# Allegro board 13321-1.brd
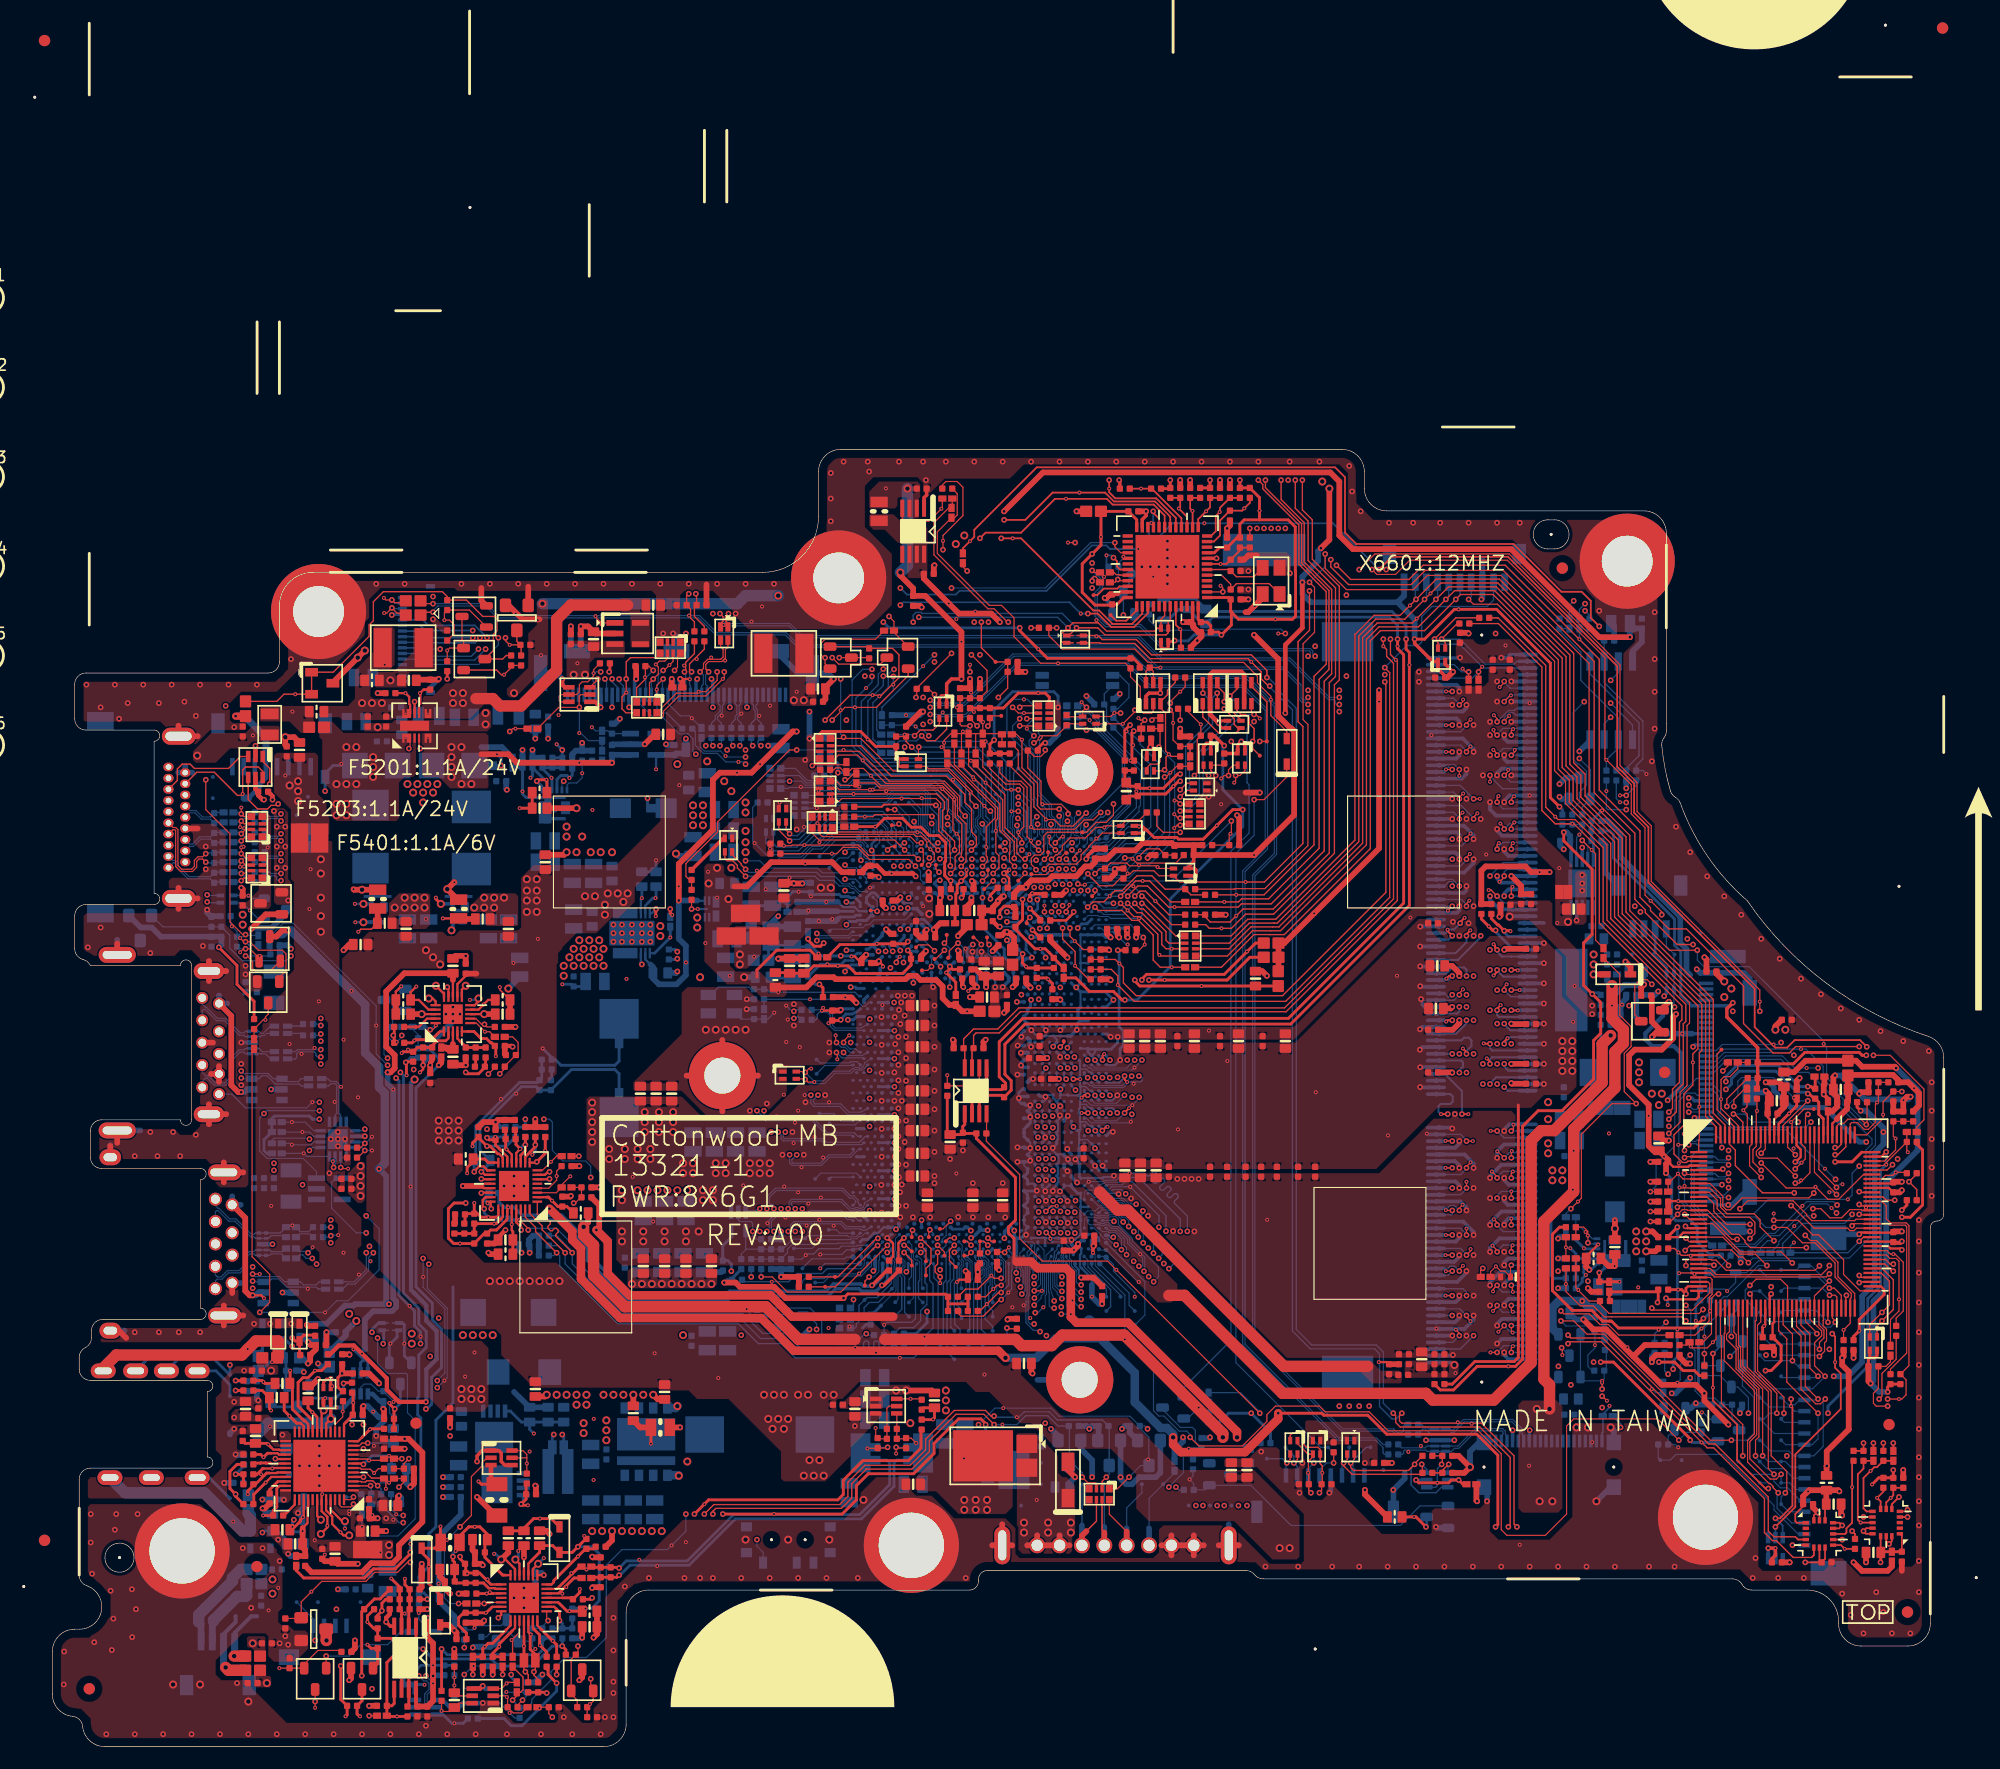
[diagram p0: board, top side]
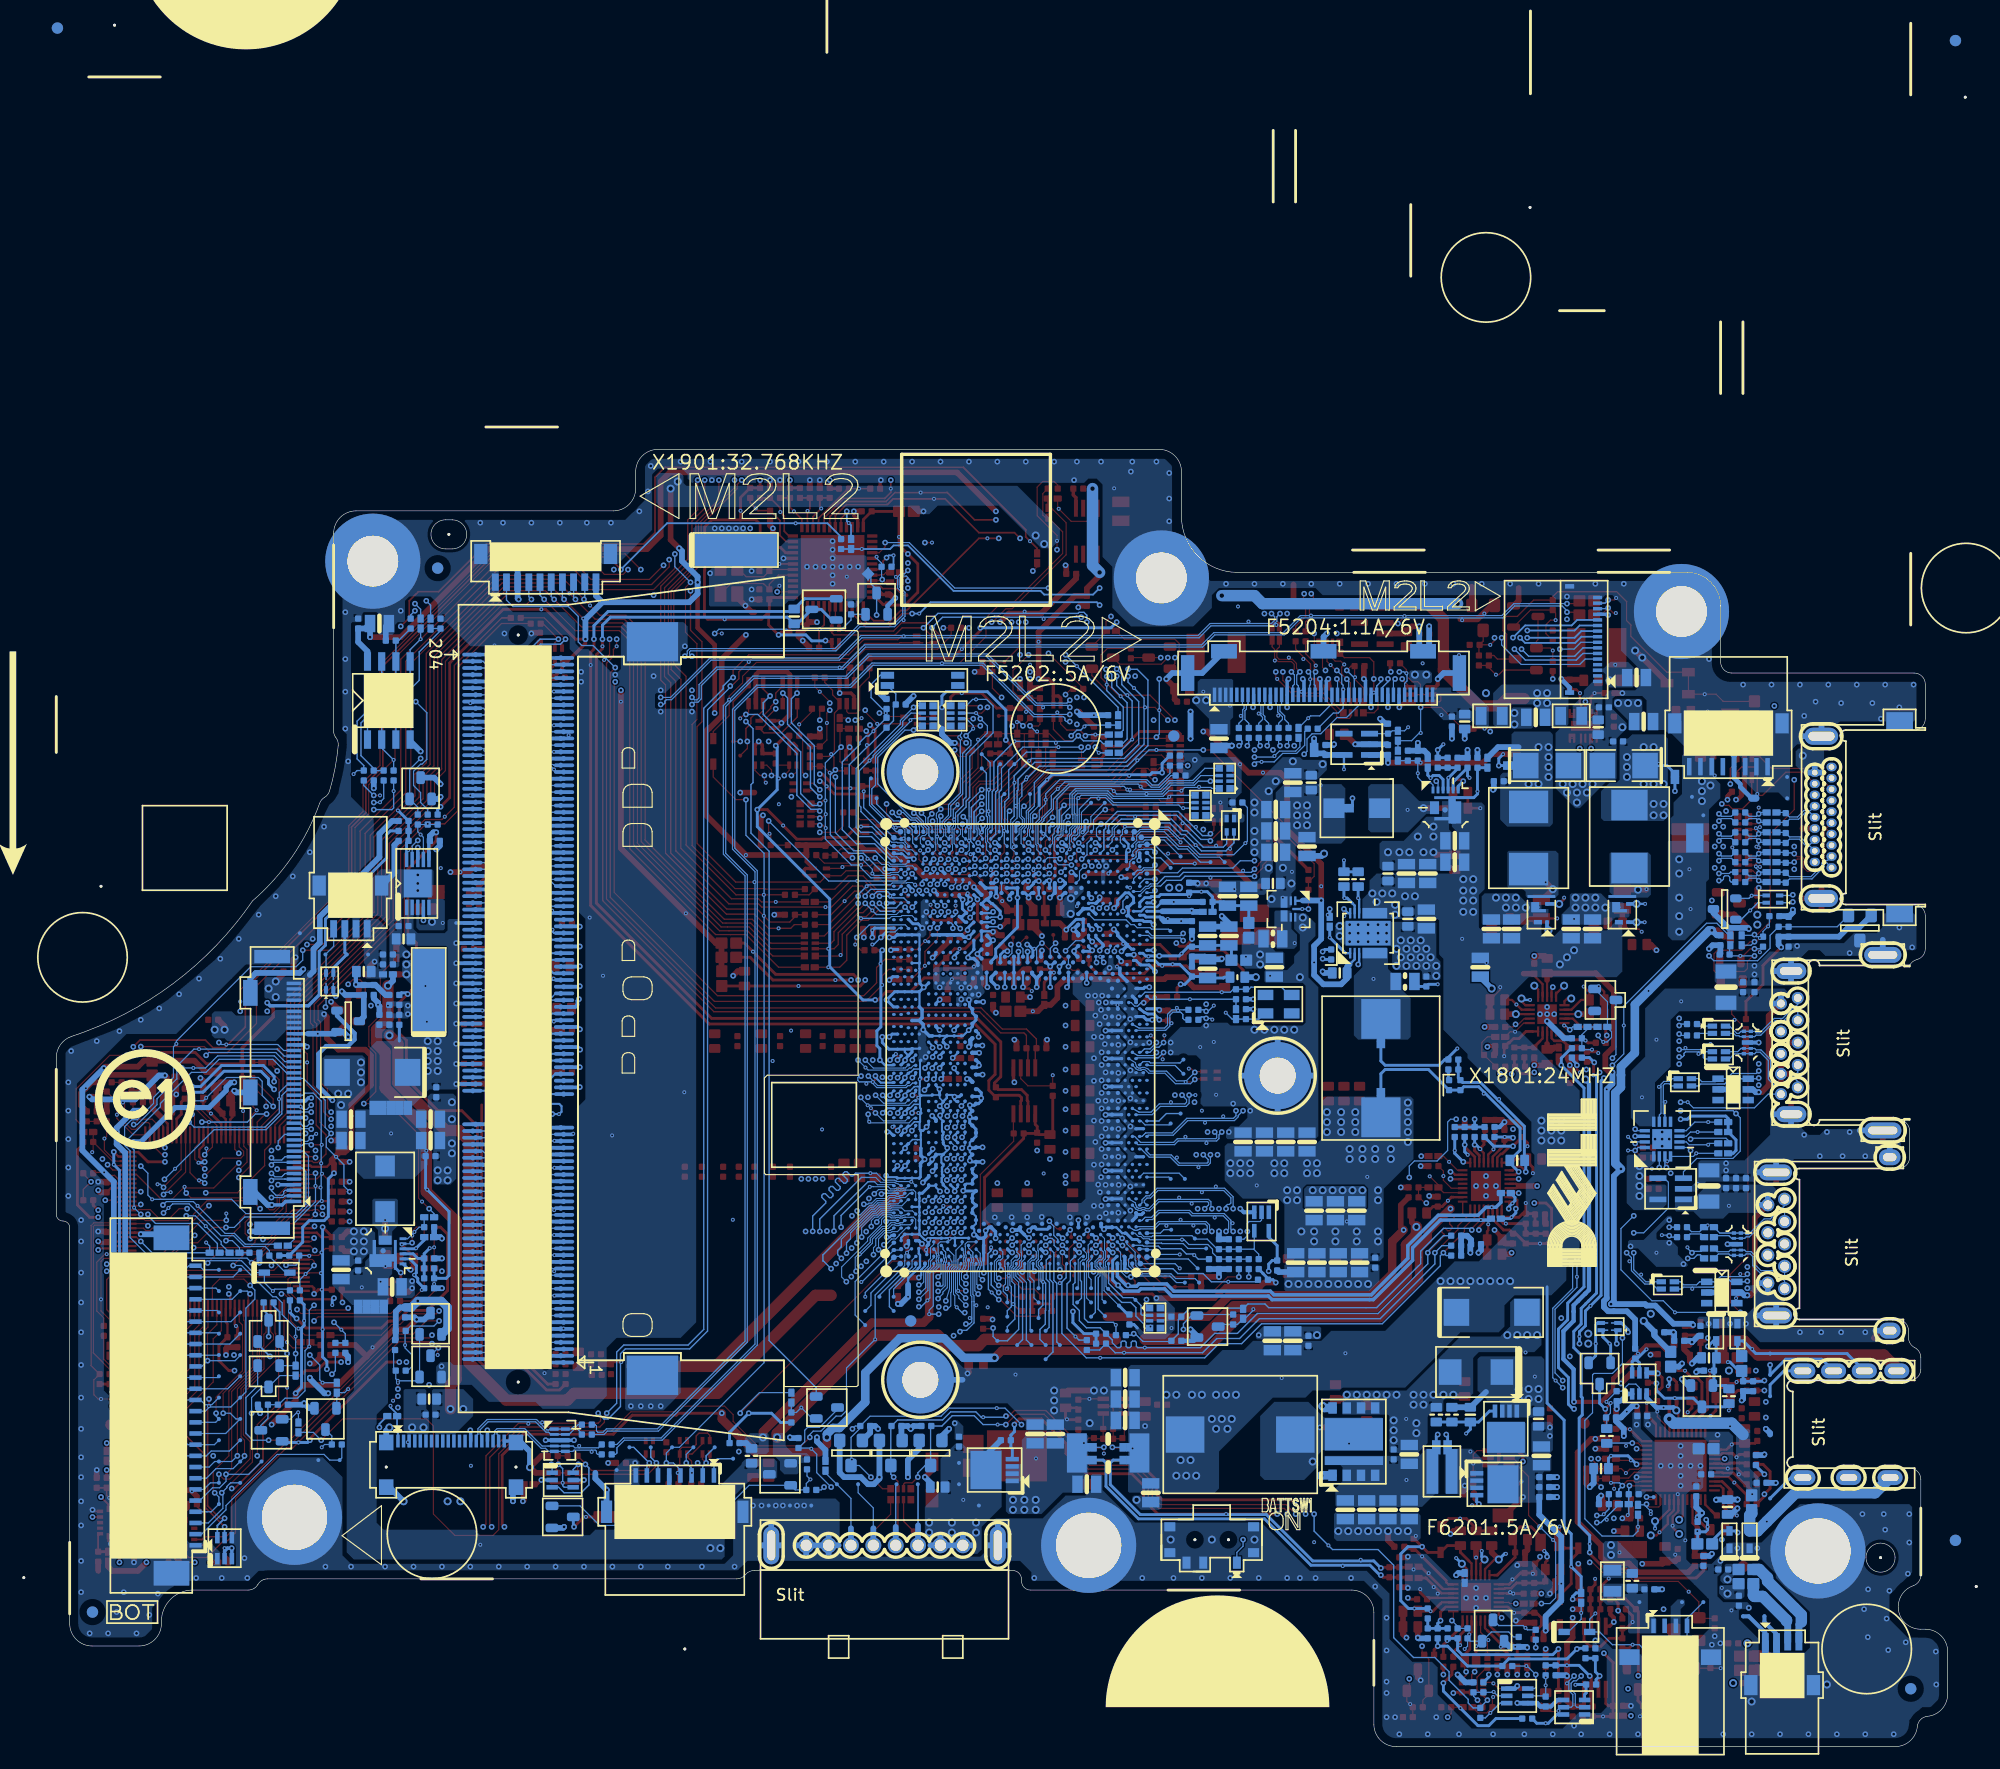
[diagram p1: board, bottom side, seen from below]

Outline 169.1 x 116 mm; copper layers: TOP, L2VCC, L3, L4, L5GND, BOTTOM. Coordinates in mm from the lower left corner of the outline.
Outline path: 0,8.5 0,4.7 arc(0.52,3.35) 1.81,2.71 arc(2.42,2.42) 2.71,1.81 arc(3.35,0.52) 4.7,0 49.3,0 arc(50.71,0.59) 51.3,2 51.3,12 arc(51.89,13.41) 53.3,14 82,14 arc(82.57,14.23) 82.8,14.8 82.8,14.95 arc(83.03,15.52) 83.6,15.75 106.71,15.75 arc(107.14,15.65) 107.49,15.37 arc(107.84,15.1) 108.27,15 150.21,15 arc(150.71,14.87) 151.07,14.5 arc(151.44,14.13) 151.94,14 156.9,14 arc(158.88,13.18) 159.7,11.2 159.7,11 arc(160.29,9.59) 161.7,9 165.9,9 arc(167.31,9.59) 167.9,11 167.9,46.4 arc(168.08,46.82) 168.5,47 arc(168.92,47.18) 169.1,47.6 169.1,61.61 arc(168.72,62.78) 167.72,63.51 arc(158.64,68.24) 151.55,75.63 arc(147.99,79.61) 145.55,84.36 arc(145.38,84.66) 145.12,84.88 arc(144.84,85.13) 144.67,85.46 arc(144.18,87.47) 143.89,89.52 arc(143.93,89.89) 144.1,90.23 arc(144.26,90.53) 144.31,90.87 arc(144.3,91.18) 144.3,91.5 144.3,108.5 arc(143.71,109.91) 142.3,110.5 119.3,110.5 arc(117.89,111.09) 117.3,112.5 117.3,114 arc(116.71,115.41) 115.3,116 70.5,116 arc(69.09,115.41) 68.5,114 68.5,110 arc(67.04,106.46) 63.5,105 23.3,105 arc(21.18,104.12) 20.3,102 20.3,97 arc(20.01,96.29) 19.3,96 3,96 arc(2.29,95.71) 2,95 2,91.9 arc(2.29,91.19) 3,90.9 9.1,90.9 arc(9.6,90.4) 9.1,89.9 9.1,76.3 arc(9.6,75.8) 9.1,75.3 3,75.3 arc(2.29,75.01) 2,74.3 2,71.35 arc(2.21,70.74) 2.75,70.38 arc(3.13,70.19) 3.4,69.85 11.45,69.85 arc(11.95,70.35) 12.45,69.85 12.45,56.05 arc(11.95,55.55) 11.45,56.05 4.4,56.05 arc(3.69,55.76) 3.4,55.05 3.4,52.7 arc(3.69,51.99) 4.4,51.7 13.25,51.7 arc(13.75,51.2) 13.25,50.7 13.25,39.2 arc(13.75,38.7) 13.25,38.2 4.5,38.2 arc(3.79,37.91) 3.5,37.2 3.5,36.58 arc(3.35,36.05) 2.95,35.68 arc(2.55,35.31) 2.4,34.79 2.4,33.75 arc(2.69,33.04) 3.4,32.75 13.85,32.75 arc(14.35,32.25) 13.85,31.75 13.85,25.9 arc(14.35,25.4) 13.85,24.9 3.4,24.9 arc(2.69,24.61) 2.4,23.9 2.4,15.34 arc(2.59,14.76) 3.07,14.39 arc(4.39,12.17) 2.42,10.5 2,10.5 arc(0.59,9.91) 0,8.5 ; 4.7,16.9 arc(6,18.2) 7.3,16.9 arc(6,15.6) 4.7,16.9 ; 8.7,17.5 arc(11.6,20.4) 14.5,17.5 arc(11.6,14.6) 8.7,17.5 ; 21.55,101.5 arc(23.8,103.75) 26.05,101.5 arc(23.8,99.25) 21.55,101.5 ; 58.3,60 arc(59.9,61.6) 61.5,60 arc(59.9,58.4) 58.3,60 ; 68.05,104.5 arc(70.3,106.75) 72.55,104.5 arc(70.3,102.25) 68.05,104.5 ; 73.9,18 arc(76.8,20.9) 79.7,18 arc(76.8,15.1) 73.9,18 ; 90.25,87.15 arc(91.85,88.75) 93.45,87.15 arc(91.85,85.55) 90.25,87.15 ; 90.25,32.8 arc(91.85,34.4) 93.45,32.8 arc(91.85,31.2) 90.25,32.8 ; 133.7,109.7 134.3,109.7 arc(135.6,108.4) 134.3,107.1 133.7,107.1 arc(132.4,108.4) 133.7,109.7 ; 138.55,106 arc(140.8,108.25) 143.05,106 arc(140.8,103.75) 138.55,106 ; 144.9,20.5 arc(147.8,23.4) 150.7,20.5 arc(147.8,17.6) 144.9,20.5

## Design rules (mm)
constraint set DEFAULT: min track width 0.127, pair gap 0.102
net group 85_USB6-DIFF165: nets USB_PN6 USB_PP6
net group AUDIO_SLEEVE-MWS: nets RING2_R SLEEVE_R
net group CLK_PCI_KBC: nets CLK_PCI_KBC CLK_PCI_KBC_R
net group CLK_PCI_LPC: nets CLK_PCI_LPC CLK_PCI_LPC_R
net group EDP_AUX: nets EDP_AUX EDP_AUX_DP
net group EDP_AUX#: nets EDP_AUX# EDP_AUX_DN
net group EDP_TX0: nets EDP_TX0 EDP_TX0_DP
net group EDP_TX0#: nets EDP_TX0# EDP_TX0_DN
net group EDP_TX1: nets EDP_TX1 EDP_TX1_DP
net group EDP_TX1#: nets EDP_TX1# EDP_TX1_DN
net group GND-MW: nets EC_AGND MIC_GND
net group HDA_CODEC_RST#: nets HDA_CODEC_RST# HDA_RST#
net group HDA_CODEC_SDIN0: nets HDA_CODEC_SDIN0 HDA_SDIN0
net group HDA_CODEC_SYNC: nets HDA_CODEC_SYNC HDA_SYNC
net group LPC_AD0: nets LPC_AD0 LPC_LAD0_PCH
net group LPC_AD1: nets LPC_AD1 LPC_LAD1_PCH
net group LPC_AD2: nets LPC_AD2 LPC_LAD2_PCH
net group LPC_AD3: nets LPC_AD3 LPC_LAD3_PCH
net group LPC_FRAME#: nets LPC_FRAME# LPC_LFRAME#_PCH
net group P26_FAN-MWS: nets FAN_PWM1 FAN_PWM1_C
net group PCH_SPI_DQ2: nets PCH_SPI_DQ2 SPI_WP#
net group PCH_SPI_DQ3: nets PCH_SPI_DQ3 SPI_HOLD#
net group PCIE_PTX_WLANRX_N3: nets PCIE_PTX_WLANRX_N3 PCIE_PTX_WLANRX_N3_C
net group PCIE_PTX_WLANRX_P3: nets PCIE_PTX_WLANRX_P3 PCIE_PTX_WLANRX_P3_C
net group PWR_VCC_GFB: nets PWR_VCC_GFB VSS_SENSE
net group PWR_VCC_VFB: nets PWR_VCC_VFB VCC_SENSE
net group T10_DDR3_A_ODT-MWS: nets M_A_DIMA_ODT0 M_A_DIMA_ODT1
net group USB30_RXDN1_C: nets USB3_PRX_CTX_N1 USB30_RXDN1_C
net group USB30_RXDP1_C: nets USB3_PRX_CTX_P1 USB30_RXDP1_C
net group USB30_TXDN0_R: nets USB3_PTX_CRX_N0 USB30_TXDN0_R
net group USB30_TXDP0_R: nets USB3_PTX_CRX_P0 USB30_TXDP0_R
net group USB_3+: nets USB_3+ USB_PP3
net group USB_3-: nets USB_3- USB_PN3
net group USB_PN1: nets USB_PN1 USB_PN1_R
net group USB_PP1: nets USB_PP1 USB_PP1_R
net group 50_CFG-MWS: nets CFG0 CFG1 CFG2 CFG3 CFG4 CFG5 CFG6 CFG7 CFG8 CFG9 CFG10 CFG11 CFG12 CFG13 CFG14 CFG15 CFG16 CFG17 CFG18 CFG19
net group 50_CLK-MWS: nets SUS_CLK SUS_CLK_PCH SUSCLK_KBC TP_CL_RST#
net group 50_INTEL_SIDEBAND-MWS: nets H_CATERR# H_CPUPWRGD H_PECI H_PROCHOT# H_PROCHOT#_EC H_PROCHOT#_R H_RCIN# PCH_PWROK PCH_THERMTRIP PECI PM_RSMRST# PQ4405_3 PQ4406_D PQ4413_3 PROCHOT#_BQ24770 PROCHOT_EC RTC_RST# SYS_PWROK
net group 50_JTAG-MWS: nets PCH_JTAG_TCK PCH_JTAG_TDI PCH_JTAG_TDO PCH_JTAG_TMS PCH_JTAG_TRST#
net group 50_LCD_BKLT-MWS: nets BKLT_CTRL EDP_BRIGHTNESS L_BKLT_CTRL LCD_BRIGHTNESS
net group 50_LPC-MWS: nets INT_SERIRQ
net group 50_SVID-MWS: nets H_CPU_SVIDALRT# H_CPU_SVIDCLK H_CPU_SVIDDAT VR_SVID_ALERT#
net group 50_XDP-MWS: nets XDP_DBRESET# XDP_PRDY# XDP_PREQ# XDP_TCK_JTAGX XDP_TCLK XDP_TDI XDP_TDO XDP_TMS XDP_TRST#
net group 50_XDP_BPM-MWS: nets XDP_BPM0 XDP_BPM1 XDP_BPM2 XDP_BPM3 XDP_BPM4 XDP_BPM5 XDP_BPM6 XDP_BPM7
net group 50_XTAL-MWS: nets MCU_OSCI MCU_OSCO RTC_X1 RTC_X2 XTAL24_IN XTAL24_IN_R XTAL24_OUT
net group AUDIO_OTHER-MWS: nets AMP_MUTE# COMBO-GPI EAPD# JDREF MUTE_CTRL
net group AUDIO_POWER_20-MW: nets +3V_1D5V_AVDD
net group AUDIO_T10_BEEP-MWS: nets AUD_HP1_JACK_L AUD_HP1_JACK_L1 AUD_HP1_JACK_R AUD_HP1_JACK_R1 AUD_PC_BEEP AUD_PC_BEEP_C AUD_PORTA_L_R_B AUD_PORTA_R_R_B AUD_SENSE AUD_SENSE_A AUD_VREF CBN CBP CPVEE HDA_SPKR HDA_SPKR_R JACK_PLUG JACK_POWER KBC_BEEP KBC_BEEP_R LDO1_CAP LDO2_CAP LDO3_CAP LINE1-L_C LINE1-L_R LINE1_L LINE1_R LINE1_VREFO_L LINE1_VREFO_R MIC2_VREFO MIC_CAP SLEEVE_CTRL V3D3_STB
net group AUDIO_T40_SPK-MWS: nets AUD_SPK_L+_C AUD_SPK_L-_C AUD_SPK_R+_C AUD_SPK_R-_C
net group CODEC_BITCLK_R: nets CODEC_BITCLK_R HDA_BITCLK HDA_CODEC_BITCLK
net group CODEC_SDOUT_R: nets CODEC_SDOUT_R HDA_CODEC_SDOUT HDA_SDOUT
net group EC_SPI_CLK_C: nets EC_SPI_CLK_C PCH_SPI_CLK SPI_CLK_R
net group EC_SPI_CS#_C: nets EC_SPI_CS#_C PCH_SPI_CS0# SPI_CS0#_R
net group EC_SPI_DI_C: nets EC_SPI_DI_C PCH_SPI_SI SPI_SI_R
net group EC_SPI_DO_C: nets EC_SPI_DO_C PCH_SPI_SO SPI_SO_R
net group FFS-MW: nets FFS_INT2 FFS_INT2_Q FFS_INT2_Q_R HDD_FALL_INT INT2_SELECT
net group HDMI_CLK: nets HDMI_CLK HDMI_CLK_R HDMI_CLK_R_C
net group HDMI_CLK#: nets HDMI_CLK# HDMI_CLK#_R HDMI_CLK#_R_C
net group HDMI_DATA0: nets HDMI_DATA0 HDMI_DATA0_R HDMI_DATA0_R_C
net group HDMI_DATA0#: nets HDMI_DATA0# HDMI_DATA0#_R HDMI_DATA0#_R_C
net group HDMI_DATA1: nets HDMI_DATA1 HDMI_DATA1_R HDMI_DATA1_R_C
net group HDMI_DATA1#: nets HDMI_DATA1# HDMI_DATA1#_R HDMI_DATA1#_R_C
net group HDMI_DATA2: nets HDMI_DATA2 HDMI_DATA2_R HDMI_DATA2_R_C
net group HDMI_DATA2#: nets HDMI_DATA2# HDMI_DATA2#_R HDMI_DATA2#_R_C
net group OTHER_4MIL-MWS: nets AC_IN# AC_PRESENT ACAV_IN AD_IA AD_IA_HW AD_IA_HW2 ALS_INT# BOARD_ID1 CAMERA_DET# DBC_EN DBC_EN_R DC_TEST_A3_B3 DC_TEST_A61_B61 DC_TEST_AY2_AW2 DC_TEST_AY3_AW3 DC_TEST_AY61_AW61 DC_TEST_AY62_AW62 DC_TEST_B62_B63 DC_TEST_C1_C2 DDPC_CTRLDATA EDP_HPD EDP_HPD_CONN EDP_SPARE HDMI_HPD_B HDMI_HPD_E HDMI_PCH_DET HPD_HDMI_CON HSIOPC HSIOPC_R HVM_CLK HVM_CLK# INT_TP#_C KB_LED_BL_DET KBC_ON#_GATE KBC_ON#_GATE_L KBC_PWRBTN# LID_CLOSE# LPSS_GSPI0_MOSI_BBS0_R LPSS_SDIO_D0_CMNHDR ME_UNLOCK NC#4 PBAT_PRES1# PCI_PME# PM_SLP_A# PM_SLP_LAN# PQ3802_1 PSID_DISABLE#_R_C RSVDA51 RSVDAU63 RSVDAV63 RSVDB51 RSVDC62 RSVDC63 RSVDL60 RSVDN59 RSVDN61 RSVDP60 RSVDP61 SA0_DIMA SA1_DIMA SYS_PRES1# TOUCH_PANEL_INTR# TP_M_A_DIMA_ODT0 TP_V1.05S_APLLOPI TP_V1.05S_AXCK_DCB TP_V1.05S_SSCF100 TP_V1.05S_SSCFF TP_VCCAPLLOPI_VAL TP_VCCIO_OUT USB_DET# USBDET_CON# VOL_DOWN# VOL_UP#
net group OTHER_EC-MWS: nets BAT_IN# BLON_OUT BLON_OUT_C E51_TXD EC_GPIO10 EC_SCI# EC_SMI# EC_SWI# ECRST# ECSCI#_KBC ECSMI#_KBC HDMI_EC_DET# HDMI_EC_DET#_C HOME_BTN# HOME_BTN#_C HPD_HDMI_CON_C KB_CLOSE#_2 KB_DISABLE L_BKLT_EN_EC LCD_TST LCD_TST_C LCD_TST_EN MODEL_ID_DET PANEL_SIZE PCB_VER_AD PCIE_WAKE# PM_CLKRUN# PM_CLKRUN#_EC PM_PWRBTN# PM_SLP_SUS# PSL_IN1# PSL_IN2# PSL_OUT# RTC_DET# TP_LOCK# TP_LOCK#_C TP_WAKE_KBC#
net group OTHER_PCH-MWS: nets BATLOW# CLK_PCIE_REQ# CLK_PCIE_WLAN_REQ3# COLOR_ENGINE HDD_DEVSLP INT_TP# L_BKLT_EN MCP_GPIO0 MCP_GPIO1 MCP_GPIO8 MCP_GPIO11 MCP_GPIO12 MCP_GPIO13 MCP_GPIO14 MCP_GPIO15 MCP_GPIO16 MCP_GPIO17 MCP_GPIO26 MCP_GPIO27 MCP_GPIO28 MCP_GPIO35 MCP_GPIO36 MCP_GPIO37 MCP_GPIO38 MCP_GPIO44 MCP_GPIO45 MCP_GPIO46 MCP_GPIO47 MCP_GPIO50 MCP_GPIO51 MCP_GPIO52 MCP_GPIO54 MCP_GPIO55 MCP_GPIO56 MCP_GPIO59 MCP_GPIO68 MCP_GPIO70 MCP_GPIO73 MCP_GPIO90 MCP_R MCP_TESTLOW1 MCP_TESTLOW2 MCP_TESTLOW3 MCP_TESTLOW4 PCH_INTVRMEN PCH_WAKE# PIRQA# PIRQB# PIRQC# PIRQD# SM_INTRUDER# TP_DC_TEST_A4 TP_DC_TEST_A60 TP_DC_TEST_A62 TP_DC_TEST_AV1 TP_DC_TEST_AW1 TP_DC_TEST_AW63 TP_DC_TEST_AY60 TP_DC_TEST_B2 TP_HDA_DOCK_EN# USB_OC#0_1 USB_OC#2_3 USB_OC#4_5 USB_OC#6_7
net group OTHER_POWER-MWS: nets +VCHGR_R AD+_G_1 DCBATOUT_R N29302517 PD4403_A PD4403_K PQ4405_2 PQ4405_5 PQ4405_6 PQ4406_G PQ4408_C PQ4408_E PQ4413_5 PU4401_4 PU4401_5 PWR_CHG_ACOK
net group OTHER_USB_CHARGER-MWS: nets CTL1 CTL2 CTL3 ILIM_HI ILIM_LO ILIM_SEL USB_CHG_EN USBCHARGER_CB0
net group PLATFORM-MWS: nets DDR3_DRAMRST# DDR_PG_CTRL DDR_PG_CTRL_R DDR_VTT_PG_CTRL DS3_PWRCTL KBC_DPWROK MPWROK PCH_DPWROK PCH_SLP_S0# PCH_SLP_WLAN# PCI_PLTRST# PM_PCH_PWROK PM_SLP_S3# PM_SLP_S4# PM_SLP_S5# PM_SUS_STAT# PM_SUSACK# PM_SUSACK#_R PM_SUSWARN# PM_SUSWARN#_R PS_S3CNTRL PU4401_6 PU4902_S5 RSMRST#_KBC RTCRST_ON SATA_ODD_PWRGT SM_DRAMRST# SRTC_RST#
net group POWER4: nets +V1.05A_AOSCSUS +V1.05A_SUS_PCH +V1.05A_USB2SUS +V1.05A_VCCUSB3SUS
net group POWER10: nets 3D3V_GSEN2 3D3V_MCU 3V5V_CT1 3V5V_CT2 +3.3A_DSW_PRTCSUS +PCH_VCCDSW +V1.05S_ASATA3PLL +V1.05S_AUSB3PLL +V1.05S_AXCK_DCB +V1.05S_AXCK_LCPLL +V1.05S_SSCF100 +V1.05S_SSCFF +V3.3A_DSW_P +V3.3A_PSUS +V3.3S_1.8S_LPSS_SDIO +V3.3S_PCORE +VCCRTCEXT AD+_G_2 DIS_DTM_CELL EC_VBKUP
net group POWER20: nets 3D3V_PWR_2 3D3V_RUN_FFS 5V_PWR_2 +V1.05S_AIDLE +V3.3A_1.5A_HDA +VCCIOA_OUT DCBATOUT_SNUB DDR_VREF_S3
net group POWER40: nets 1D5V_PWR 1D5V_S0 +1.05M_ASW M_A_B_DIMM_ODT
net group POWER_T10: nets 1D05V_PWR_BS 1D05V_PWR_BS_R 1D05V_PWR_BYP 1D05V_PWR_FB 1D05V_PWR_FBH 1D05V_PWR_LDO 3V_FEEDBACK BATDRV# BOOST_MON BOOST_MON_1 BQ24770_IADP BQ24770_IDCHG BQ24770_PMON CHARGER_CELL_PIN CHG_CMPIN_1 CHG_CMPOUT_1 N172633395 P_SYS PQ4401_D PQ4401_G PQ4411_D1 PQ4411_D2 PU4402_1IN+ PU4402_1IN- PU4902_VCNTL PWR_1D05V_PWR_ILIM PWR_1D35V_BYP PWR_1D35V_IMAX PWR_1D35V_LDO_P5 PWR_1D35V_VFB PWR_3D3V_CS2 PWR_3D3V_FB2 PWR_3D3V_FB2_R PWR_5V_CS1 PWR_5V_FB1 PWR_5V_FB1_R PWR_5V_VCLK PWR_CHG_1 PWR_CHG_ACDET PWR_CHG_BAT PWR_CHG_BATDRV PWR_CHG_BTST1 PWR_CHG_CMPIN PWR_CHG_CMPOUT PWR_CHG_CMSRC PWR_CHG_REGN PWR_CHG_VCC PWR_VCC_B-RAMP PWR_VCC_BOOT1 PWR_VCC_BOOTR1 PWR_VCC_COMP PWR_VCC_CSN1 PWR_VCC_CSP1 PWR_VCC_DROOP PWR_VCC_F-IMAX PWR_VCC_IMON PWR_VCC_O-USR PWR_VCC_OCP-1 PWR_VCC_PWM1 PWR_VCC_SKIP# PWR_VCC_SKIP#1 PWR_VCC_SLEWA PWR_VCC_THERM PWR_VCC_V5A PWR_VCC_VBAT PWR_VCC_VDD PWR_VCC_VREF Q6204_G Q6205_Q VCC_BOOTR1_R VCC_CSN1_R VCC_VSW1_GP VCC_VSW1_R
net group POWER_T20: nets 3D3V_AUX_KBC_VCC 3D3V_AUX_S5 +RTC_VCC +V_VREF_PATH1 +V_VREF_PATH3 DC_IN_D EC_VTT FALL_INT2 PWR_1D35V_BOOT PWR_1D35V_BOOT_R PWR_3D3V_SNUB PWR_3D3V_VBST2 PWR_3D3V_VBST2_1 PWR_5V_SNUB PWR_5V_VBST1 PWR_5V_VBST1_1 PWR_5V_VO1 PWR_CHG_BTST PWR_DEBUG RTC_AUX_S5 VBAT
net group POWER_T40: nets PWR_3D3V_DRVH2 PWR_3D3V_DRVL2 PWR_5V_DRVH1 PWR_5V_DRVL1 PWR_CHG_HIDRV PWR_CHG_LODRV
net group REF10M-MWS: nets KBC_VCORF
net group SATA3_PRX_HDDTX_N0: nets SATA3_PRX_HDDTX_N0
net group SATA3_PRX_HDDTX_P0: nets SATA3_PRX_HDDTX_P0
net group SATA3_PTX_HDDRX_N0: nets SATA3_PTX_HDDRX_N0
net group SATA3_PTX_HDDRX_P0: nets SATA3_PTX_HDDRX_P0
net group SENSOR: nets FFS_INT1_D FFS_INT2_D GSEN2_INT1 GSEN2_INT1_C GSEN2_INT2 GSEN2_INT2_C GSEN_INT1 GSEN_INT2 GSENSOR_CS GSENSOR_SDO GYRO_DRDY GYRO_INT GYRO_INT_C GYRO_INT_P11 HUB_PA1 HUB_PA2 HUB_PA3 HUB_PA4 HUB_PA5 HUB_PA6 MCU_BOOT0 MCU_RST# SWCLK SWDIO USBDISABLE
net group T4.5_PSID-MWS: nets PS_ID PS_ID_R2 PSID_EC
net group T4_KB-MWS: nets KB_BL_CTRL KCOL0 KCOL1 KCOL2 KCOL3 KCOL4 KCOL5 KCOL6 KCOL7 KCOL8 KCOL9 KCOL10 KCOL11 KCOL12 KCOL13 KCOL14 KCOL15 KCOL16 KROW0 KROW1 KROW2 KROW3 KROW4 KROW5 KROW6 KROW7
net group T4_LED-MW: nets BATT_WHITE_LED# CAP_LED CAP_LED# CAP_LED_Q CAP_LED_R# CHG_AMBER_LED# SATA_LED#
net group T4_PWRGD-MWS: nets 1D05V_VTT_PWRGD 1D35V_VTT_PWRGD 3V5V_S0_ON 3V_5V_EN 3V_5V_POK 3V_5V_POK# 3V_5V_POK_C ALL_SYS_PWRGD BLUETOOTH_EN CAMERA_PWR_EN CARD_PWR_EN DSWODVREN EDP_VDD_EN H_VCCST_PWRGD H_VR_ENABLE IMVP_PWRGD IMVP_PWRGD_R IMVP_VRON LVDS_VDD_EN_R PLT_RST# PLT_RST#_EC PWR_1D5V_EN PWR_1D05V_PWR_EN PWR_1D35V_EN PWR_1D35V_PGOOD PWR_3D3V_EN2 PWR_5V_EN1 PWR_5V_EN1_R PWR_PG S5_ENABLE SENSOR_HUB_RST# TP_ON# TP_ON#_GATE USB_PWR_EN# VTT_EN WIFI_RF_EN
net group T10_FAN_TACH-MWS: nets FAN_TACH1 FAN_TACH1_C VD1_EN# VD_OUT1#
net group T10_PCH-MWS: nets PCH_VCCDSW_R
net group T20_COMP: nets CFG_RCOMP EDP_COMP PCH_OPIRCOMP PCIE_RCOMP PROC_OPI_COMP PROC_OPI_COMP3 PWR_VCC_COMP_1 SATA_IREF SATA_RCOMP SM_RCOMP_0 SM_RCOMP_1 SM_RCOMP_2 TD_IREF USB_COMP XCLK_BIASREF
net group T25_PSID-MW: nets PS_ID_R
net group THERM_SHUTDOWN-MWS: nets ALERT# PURE_HW_SHUTDOWN# T_CRIT# THERM_SYS_SHDN#
net group USB30_TXDN1_C: nets USB3_PTX_CRX_N1 USB30_TXDN1_C USB30_TXDN1_R
net group USB30_TXDP1_C: nets USB3_PTX_CRX_P1 USB30_TXDP1_C USB30_TXDP1_R

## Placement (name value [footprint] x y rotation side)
AFTP2601  AFTE14P-GP  [AFTE14P-75]  143.13 70.83 180 bottom
AFTP2602  AFTE14P-GP  [AFTE14P-75]  145.03 70.83 180 bottom
AFTP2603  AFTE14P-GP  [AFTE14P-75]  141.22 70.83 180 bottom
AFTP2604  AFTE14P-GP  [AFTE14P-75]  147.32 72.74 180 bottom
AFTP2901  AFTE14P-GP  [AFTE14P-75]  13.72 12.41 180 bottom
AFTP2902  AFTE14P-GP  [AFTE14P-75]  17.27 13.43 180 bottom
AFTP2903  AFTE14P-GP  [AFTE14P-75]  16.38 11.65 180 bottom
AFTP2904  AFTE14P-GP  [AFTE14P-75]  18.29 11.65 180 bottom
AFTP2906  AFTE14P-GP  [AFTE14P-75]  15.88 22.19 270 bottom
AFTP2907  AFTE14P-GP  [AFTE14P-75]  15.88 35.15 180 bottom
AFTP2908  AFTE14P-GP  [AFTE14P-75]  15.88 27.91 270 bottom
AFTP2909  AFTE14P-GP  [AFTE14P-75]  15.88 33.24 270 bottom
AFTP2910  AFTE14P-GP  [AFTE14P-75]  15.88 31.34 180 bottom
AFTP4201  AFTE14P-GP  [AFTE14P-75]  22.86 84.93 180 bottom
AFTP4202  AFTE14P-GP  [AFTE14P-75]  21.84 83.28 180 bottom
AFTP4203  AFTE14P-GP  [AFTE14P-75]  17.14 84.8 180 bottom
AFTP4204  AFTE14P-GP  [AFTE14P-75]  14.35 86.71 180 bottom
AFTP4205  AFTE14P-GP  [AFTE14P-75]  14.35 84.8 180 bottom
AFTP4301  AFTE14P-GP  [AFTE14P-75]  97.41 23.46 180 bottom
AFTP4302  AFTE14P-GP  [AFTE14P-75]  93.98 23.46 180 bottom
AFTP4303  AFTE14P-GP  [AFTE14P-75]  92.08 23.46 180 bottom
AFTP4304  AFTE14P-GP  [AFTE14P-75]  99.31 23.46 180 bottom
AFTP4305  AFTE14P-GP  [AFTE14P-75]  88.39 25.37 180 bottom
AFTP4306  AFTE14P-GP  [AFTE14P-75]  88.39 23.46 180 bottom
AFTP4307  AFTE14P-GP  [AFTE14P-75]  86.61 21.56 180 bottom
AFTP4308  AFTE14P-GP  [AFTE14P-75]  103.5 21.56 180 bottom
AFTP4309  AFTE14P-GP  [AFTE14P-75]  105.41 21.56 180 bottom
AFTP4310  AFTE14P-GP  [AFTE14P-75]  101.6 21.56 180 bottom
AFTP4501  AFTE14P-GP  [AFTE14P-75]  32.51 64.36 90 top
AFTP6201  AFTE14P-GP  [AFTE14P-75]  152.65 42.64 270 bottom
AFTP6202  AFTE14P-GP  [AFTE14P-75]  154.56 40.73 270 bottom
AFTP6203  AFTE14P-GP  [AFTE14P-75]  154.56 38.83 270 bottom
AFTP6206  AFTE14P-GP  [AFTE14P-75]  152.65 36.92 270 bottom
AFTP6207  AFTE14P-GP  [AFTE14P-75]  154.56 35.02 270 bottom
AFTP6208  AFTE14P-GP  [AFTE14P-75]  152.65 33.11 270 bottom
AFTP6210  AFTE14P-GP  [AFTE14P-75]  152.65 31.21 270 bottom
AFTP6211  AFTE14P-GP  [AFTE14P-75]  154.56 29.3 270 bottom
AFTP6212  AFTE14P-GP  [AFTE14P-75]  154.56 27.4 270 bottom
AFTP6213  AFTE14P-GP  [AFTE14P-75]  152.65 29.3 270 bottom
AFTP6214  AFTE14P-GP  [AFTE14P-75]  152.65 27.4 270 bottom
AFTP6215  AFTE14P-GP  [AFTE14P-75]  152.65 35.02 270 bottom
AFTP6216  AFTE14P-GP  [AFTE14P-75]  154.56 31.21 270 bottom
AFTP6217  AFTE14P-GP  [AFTE14P-75]  154.56 36.92 270 bottom
AFTP6218  AFTE14P-GP  [AFTE14P-75]  154.56 25.49 270 bottom
AFTP6219  AFTE14P-GP  [AFTE14P-75]  154.56 33.11 180 bottom
AFTP6220  AFTE14P-GP  [AFTE14P-75]  152.65 23.59 270 bottom
AFTP6221  AFTE14P-GP  [AFTE14P-75]  152.65 25.49 270 bottom
AFTP6222  AFTE14P-GP  [AFTE14P-75]  154.56 23.59 270 bottom
AFTP6223  AFTE14P-GP  [AFTE14P-75]  152.65 40.73 270 bottom
AFTP6224  AFTE14P-GP  [AFTE14P-75]  150.75 25.49 270 bottom
AFTP6225  AFTE14P-GP  [AFTE14P-75]  154.56 21.68 270 bottom
AFTP6226  AFTE14P-GP  [AFTE14P-75]  145.67 25.62 180 bottom
AFTP6227  AFTE14P-GP  [AFTE14P-75]  152.65 38.83 180 bottom
AFTP6228  AFTE14P-GP  [AFTE14P-75]  154.56 42.64 180 bottom
AFTP6229  AFTE14P-GP  [AFTE14P-75]  21.84 12.92 180 bottom
AFTP6233  AFTE14P-GP  [AFTE14P-75]  143.76 25.62 270 bottom
AFTP6235  AFTE14P-GP  [AFTE14P-75]  120.9 24.48 180 bottom
AFTP6236  AFTE14P-GP  [AFTE14P-75]  110.24 26.76 180 bottom
AFTP6237  AFTE14P-GP  [AFTE14P-75]  115.95 26.76 180 bottom
AFTP6238  AFTE14P-GP  [AFTE14P-75]  108.58 25.75 180 bottom
AFTP6239  AFTE14P-GP  [AFTE14P-75]  119 24.73 180 bottom
AFTP6240  AFTE14P-GP  [AFTE14P-75]  117.86 26.76 180 bottom
AFTP6241  AFTE14P-GP  [AFTE14P-75]  114.05 26.76 180 bottom
AFTP6242  AFTE14P-GP  [AFTE14P-75]  112.14 26.76 180 bottom
AFTP6247  AFTE14P-GP  [AFTE14P-75]  23.75 12.92 180 bottom
AFTP6248  AFTE14P-GP  [AFTE14P-75]  27.56 12.92 180 bottom
BATSW1  SW-SLIDE77-GP  [NSS507-212F-BAAG1W-A]  65.8 18.5 0 bottom
BATT1  ALP-CON8-17-GP-U1  [C144KA-108A7-L-1]  95.05 18 180 bottom
C701  SC22U6D3V3MX-1-GP  [C603H40]  83.57 67.02 270 top
C702  SCD1U10V2KX-5GP  [C402H22]  59.94 43.02 180 bottom
C703  SC1U6D3V2KX-GP  [C402H22]  85.34 66.77 0 top
C1001  SC10U6D3V3MX-GP  [C603H38]  98.68 51.53 0 top
C1002  SC10U6D3V3MX-GP  [C603H38]  95.89 51.53 0 top
C1003  SC10U6D3V3MX-GP  [C603H38]  99.06 63.09 180 top
C1004  SC10U6D3V3MX-GP  [C603H38]  97.66 63.09 180 top
C1005  SC10U6D3V3MX-GP  [C603H38]  97.28 51.53 0 top
C1006  SC10U6D3V3MX-GP  [C603H38]  96.27 63.09 180 top
C1017  SC2D2U6D3V2MX-GP  [C402H22]  92.2 53.05 0 top
C1018  SC2D2U6D3V2MX-GP  [C402H22]  88.27 63.09 180 top
C1019  SC2200P50V2KX-2GP  [C402H22]  87.76 61.56 90 top
C1020  SC2200P50V2KX-2GP  [C402H22]  88.85 59.71 90 top
C1101  SC1U6D3V2KX-GP  [C402H22]  78.36 77.06 180 top
C1102  SC1U6D3V2KX-GP  [C402H22]  77.22 73.37 0 top
C1103  SC1U6D3V2KX-GP  [C402H22]  67.56 71.09 180 bottom
C1104  SC10U6D3V5KX-1GP  [C805H54]  64.26 72.48 0 bottom
C1105  SC1U6D3V2KX-GP  [C402H22]  67.82 76.8 0 bottom
C1106  SC10U6D3V5KX-1GP  [C805H54]  64.39 76.04 0 bottom
C1107  SC10U6D3V5KX-1GP  [C805H54]  62.48 76.04 0 bottom
C1108  SC10U6D3V3MX-GP  [C603H38]  107.57 68.67 180 top
C1109  SC1U6D3V2KX-GP  [C402H22]  82.17 69.94 0 top
C1110  SC10U6D3V3MX-GP  [C603H38]  83.31 69.56 0 top
C1111  SC1U6D3V2KX-GP  [C402H22]  77.22 70.45 90 top
C1112  SC10U6D3V3MX-GP  [C603H38]  65.91 69.82 180 top
C1113  SC1U6D3V2KX-GP  [C402H22]  67.56 69.31 0 bottom
C1114  SC10U6D3V5KX-1GP  [C805H54]  66.17 69.56 0 bottom
C1115  SC10U6D3V3MX-GP  [C603H38]  82.42 74.77 270 top
C1116  SC1U6D3V2KX-GP  [C402H22]  84.07 74.26 0 top
C1117  SC1U6D3V2KX-GP  [C402H22]  74.68 75.66 270 top
C1118  SC1U6D3V2KX-GP  [C402H22]  86.61 68.67 90 top
C1119  SC10U6D3V3MX-GP  [C603H38]  65.41 76.55 180 top
C1120  SCD1U10V2KX-5GP  [C402H22]  85.98 75.53 0 top
C1121  SCD1U10V2KX-5GP  [C402H22]  93.22 79.85 180 top
C1122  SC1U6D3V2KX-GP  [C402H22]  94.11 79.85 180 top
C1123  SC10U6D3V5KX-1GP  [C805H54]  66.17 72.48 0 bottom
C1124  SC10U6D3V3MX-GP  [C603H38]  84.58 69.56 0 top
C1125  SC10U6D3V3MX-GP  [C603H38]  67.18 69.82 180 top
C1201  SCD1U10V2KX-5GP  [C402H22]  132.21 75.79 180 top
C1202  SCD1U10V2KX-5GP  [C402H22]  129.92 75.28 270 top
C1203  SCD1U16V2KX-3GP  [C402H22]  124.08 95.6 270 top
C1204  SCD1U10V2KX-5GP  [C402H22]  123.57 34.64 180 top
C1205  SC2D2U10V3KX-1GP  [C603H36]  122.43 34.64 180 top
C1206  SCD1U10V2KX-5GP  [C402H22]  124.46 34.64 180 top
C1207  SC2D2U10V3KX-1GP  [C603H36]  123.83 69.82 90 top
C1208  SC2D2U6D3V2MX-GP  [C402H22]  135.13 58.51 180 bottom
C1209  SC2D2U10V3KX-1GP  [C603H36]  123.7 66.01 90 top
C1210  SC1KP50V2KX-1GP  [C402H22]  123.44 73.63 90 top
C1211  SCD1U10V2KX-5GP  [C402H22]  132.21 61.05 270 top
C1212  SC1U6D3V2KX-GP  [C402H22]  132.21 64.61 270 top
C1213  SC1U6D3V2KX-GP  [C402H22]  123.44 64.1 90 top
C1214  SC1U6D3V2KX-GP  [C402H22]  128.78 96.74 0 top
C1215  SC1U6D3V2KX-GP  [C402H22]  130.3 96.74 0 top
C1216  SC1U6D3V2KX-GP  [C402H22]  125.86 99.15 180 top
C1218  SCD1U10V2KX-5GP  [C402H22]  131.32 75.79 180 top
C1220  SCD1U10V2KX-5GP  [C402H22]  132.21 71.34 270 top
C1221  SCD1U10V2KX-5GP  [C402H22]  123.44 60.29 90 top
C1222  SCD1U10V2KX-5GP  [C402H22]  132.21 59.28 270 top
C1601  SCD1U10V2KX-5GP  [C402H22]  67.44 65.88 270 bottom
C1602  SCD1U10V2KX-5GP  [C402H22]  67.44 64.99 270 bottom
C1701  SC220P50V2KX-3GP  [C402H22]  82.93 94.2 180 top
C1801  SC15P50V2JN-2-GP  [C402H22]  62.74 65.5 180 bottom
C1802  SC15P50V2JN-2-GP  [C402H22]  62.74 67.28 0 bottom
C1901  SC1U6D3V2KX-GP  [C402H22]  95.76 78.07 180 top
C1902  SC1U6D3V2KX-GP  [C402H22]  94.11 78.07 0 top
C1903  SC12P50V2JN-3GP  [C402H24]  93.6 93.19 270 bottom
C1904  SC12P50V2JN-3GP  [C402H24]  94.87 93.24 180 bottom
C2101  SCD47U10V2KX-GP  [C402H22]  89.53 70.07 0 top
C2104  SC1U6D3V2KX-GP  [C402H22]  79.88 76.68 270 top
C2105  SC1U6D3V2KX-GP  [C402H22]  73.15 78.33 0 top
C2109  SC1U6D3V2KX-GP  [C402H22]  88.77 73.88 90 top
C2110  SCD1U16V2KX-3GP  [C402H22]  84.96 76.8 270 top
C2114  SC1U6D3V2KX-GP  [C402H22]  89.41 67.28 0 top
C2116  SC1U6D3V2KX-GP  [C402H22]  88.77 72.36 90 top
C2123  SC10U6D3V3MX-GP  [C603H38]  80.01 74.77 270 top
C2128  SC1U6D3V2KX-GP  [C402H22]  78.49 72.36 270 top
C2135  SC1U6D3V2KX-GP  [C402H22]  84.58 72.1 0 top
C2136  SCD1U16V2KX-3GP  [C402H22]  86.11 73.75 180 top
C2137  SC1U6D3V2KX-GP  [C402H22]  75.18 72.23 180 top
C2138  SC1U6D3V2KX-GP  [C402H22]  81.15 69.94 180 top
C2141  SC4D7U6D3V3KX-GP  [C603H36]  60.33 77.18 270 bottom
C2142  SC10U6D3V5KX-1GP  [C805H54]  60.2 69.69 180 bottom
C2147  SCD1U16V2KX-3GP  [C402H22]  81.92 76.68 270 top
C2401  SCD1U16V2KX-3GP  [C402H22]  144.02 48.74 270 top
C2402  SCD1U16V2KX-3GP  [C402H22]  162.81 58.51 90 top
C2403  SCD1U16V2KX-3GP  [C402H22]  164.59 56.36 0 top
C2404  SCD1U16V2KX-3GP  [C402H22]  160.02 57.63 270 top
C2405  SC2D2U10V3KX-1GP  [C603H36]  159.89 58.77 270 top
C2406  SCD1U16V2KX-3GP  [C402H22]  164.59 50.01 180 top
C2407  SCD1U16V2KX-3GP  [C402H22]  164.59 45.56 180 top
C2408  SCD1U16V2KX-3GP  [C402H22]  153.8 56.61 270 top
C2409  SCD1U16V2KX-3GP  [C402H22]  144.02 45.56 270 top
C2410  SCD1U16V2KX-3GP  [C402H22]  153.8 36.16 0 top
C2411  SC2D2U10V3KX-1GP  [C603H36]  154.18 57.75 270 top
C2412  SCD1U16V2KX-3GP  [C402H22]  144.02 52.29 270 top
C2413  SC2D2U10V3KX-1GP  [C603H36]  143.64 53.94 180 top
C2414  SCD1U16V2KX-3GP  [C402H22]  164.59 58.13 180 top
C2415  SC220P50V2KX-3GP  [C402H22]  144.02 50.51 90 top
C2416  SC1U6D3V2KX-GP  [C402H22]  152.91 36.16 0 top
C2417  SCD1U16V2KX-3GP  [C402H22]  138.81 35.91 0 bottom
C2418  SC1U6D3V2KX-GP  [C402H22]  48.26 2.63 90 top
C2421  SC47P50V2JN-3GP  [C402H22]  68.96 36.29 90 bottom
C2422  SC100P50V2JN-3GP  [C402H22]  143.26 35.65 180 bottom
C2501  SC10U6D3V5KX-1GP  [C805H54]  140.21 100.42 90 bottom
C2502  SCD1U16V2KX-3GP  [C402H22]  142.11 100.42 0 bottom
C2503  SCD47U10V2KX-GP  [C402H22]  141.6 67.66 0 bottom
C2601  SC10U6D3V3MX-GP  [C603H38]  80.26 54.07 0 top
C2602  SCD1U16V2KX-3GP  [C402H22]  81.41 54.45 0 top
C2603  SC2200P50V2KX-2GP  [C402H22]  139.45 70.83 90 bottom
C2604  SC4D7U6D3V3KX-GP  [C603H36]  141.6 69.31 270 bottom
C2605  SCD1U10V2KX-5GP  [C402H22]  139.45 69.94 90 bottom
C2606  SC470P50V3JN-2GP  [C603H36]  103.12 101.06 0 bottom
C2607  SC2200P50V2KX-2GP  [C402H22]  85.09 58.51 0 top
C2608  SCD1U16V2KX-3GP  [C402H22]  81.03 62.45 270 top
C2609  SCD1U16V2KX-3GP  [C402H22]  82.8 62.45 90 top
C2610  SCD1U16V2KX-3GP  [C402H22]  102.74 27.15 0 bottom
C2612  SCD1U16V2KX-3GP  [C402H22]  97.03 85.44 0 top
C2613  SC100P50V2JN-3GP  [C402H22]  157.61 58.39 180 top
C2701  SC4D7U6D3V3KX-GP  [C603H36]  19.68 21.43 180 bottom
C2702  SC10U6D3V3MX-GP  [C603H38]  18.16 27.78 0 top
C2703  SC1U10V2KX-1GP  [C402H22]  20.19 20.67 90 top
C2704  SC1U10V2KX-1GP  [C402H22]  19.43 22.19 180 top
C2705  SC2D2U6D3V2MX-GP  [C402H22]  17.53 26.13 90 top
C2706  SC4D7U6D3V3KX-GP  [C603H36]  25.27 17.24 0 top
C2707  SCD1U16V2KX-3GP  [C402H22]  24.13 17.24 0 top
C2708  SC4D7U6D3V3KX-GP  [C603H36]  28.19 19.27 90 top
C2709  SCD1U16V2KX-3GP  [C402H22]  27.94 20.41 90 top
C2710  SCD1U16V2KX-3GP  [C402H22]  18.41 29.81 180 top
C2711  SC4D7U6D3V3KX-GP  [C603H36]  17.27 30.19 180 top
C2712  SC10U6D3V3MX-GP  [C603H38]  20.57 19.4 90 top
C2713  SC10U6D3V3MX-GP  [C603H38]  22.86 31.59 180 top
C2715  SC4D7U6D3V3KX-GP  [C603H36]  21.72 18.13 270 top
C2716  SC4D7U6D3V3KX-GP  [C603H36]  30.23 21.56 90 top
C2717  SCD1U16V2KX-3GP  [C402H22]  28.32 21.68 0 top
C2718  SC4D7U6D3V3KX-GP  [C603H36]  30.99 24.86 270 bottom
C2719  SCD1U16V2KX-3GP  [C402H22]  30.1 26.64 90 top
C2720  SCD1U16V2KX-3GP  [C402H22]  30.1 28.42 270 top
C2723  SC22P50V2JN-4GP  [C402H22]  30.73 21.68 90 bottom
C2901  SC1U6D3V2KX-GP  [C402H22]  29.59 31.34 180 bottom
C2902  SC10U6D3V3MX-L-GP  [C603H38]  21.34 34.77 90 bottom
C2907  SC4D7U6D3V3KX-GP  [C603H36]  20.07 31.21 270 top
C2908  SC4D7U6D3V3KX-GP  [C603H36]  20.57 32.48 270 top
C3404  SC100U6D3V6MX-GP  [C1206H71]  19.81 67.91 0 bottom
C3405  SCD1U10V2KX-5GP  [C402H22]  22.86 64.61 90 bottom
C3406  SCD1U10V2KX-5GP  [C402H22]  22.86 63.59 90 bottom
C3407  SCD1U10V2KX-5GP  [C402H22]  23.75 45.56 90 bottom
C3408  SCD1U10V2KX-5GP  [C402H22]  23.75 46.45 90 bottom
C3409  SC100U6D3V6MX-GP  [C1206H71]  21.34 50.13 0 bottom
C3502  SCD1U16V2KX-3GP  [C402H22]  26.29 49.88 270 top
C3503  SC1U6D3V2KX-GP  [C402H22]  18.29 67.91 0 bottom
C3504  SCD1U10V2KX-5GP  [C402H22]  26.29 50.77 270 top
C3505  SCD1U10V2KX-5GP  [C402H22]  17.27 67.91 0 bottom
C3521  SC1U10V2KX-1GP  [C402H22]  19.81 50.39 0 bottom
C3522  SCD1U16V2KX-3GP  [C402H22]  18.92 50.39 0 bottom
C3601  SC10U6D3V5KX-1GP  [C805H54]  27.18 91.66 90 bottom
C3602  SC470P50V2KX-3GP  [C402H22]  30.23 94.2 270 top
C3603  SC470P50V2KX-3GP  [C402H22]  33.78 94.96 180 top
C3605  SC10U6D3V5KX-1GP  [C805H54]  36.83 92.04 270 bottom
C3701  SCD022U16V2KX-3GP  [C402H22]  140.21 64.99 0 bottom
C3702  SCD022U16V2KX-3GP  [C402H22]  119.51 33.75 180 top
C3801  SC1U10V2KX-1GP  [C402H22]  77.72 112.49 90 top
C3802  SC1U10V2KX-1GP  [C402H22]  78.36 104.87 90 top
C5202  SC4D7U25V5KX-L2-GP  [C805H58]  65.15 90.14 180 bottom
C5203  SC1KP50V2KX-L-1-GP  [C402H22]  68.45 93.44 90 top
C5204  SCD1U50V3KX-L-GP  [C603H36]  68.45 94.58 90 top
C5205  SC4D7U25V5KX-L2-GP  [C805H58]  27.81 95.6 90 bottom
C5206  SCD1U50V3KX-L-GP  [C603H36]  31.88 95.34 90 top
C5208  SCD1U10V2KX-L1-GP  [C402H22]  46.35 99.03 180 top
C5209  SC1U6D3V2KX-L-1-GP  [C402H22]  47.24 99.03 0 top
C5211  SC4D7U6D3V3KX-L-GP  [C603H36]  48.39 99.03 180 top
C5212  SC4D7U6D3V3KX-L-GP  [C603H36]  53.72 102.08 90 top
C5214  SC4D7U6D3V3KX-GP  [C603H36]  43.18 91.66 180 bottom
C5215  SC4D7U6D3V3KX-GP  [C603H36]  31.24 91.15 180 bottom
C5225  SCD1U10V2KX-5GP  [C402H22]  58.93 90.65 180 bottom
C5226  SCD1U10V2KX-5GP  [C402H22]  59.82 90.65 180 bottom
C5229  SCD1U10V2KX-5GP  [C402H22]  60.71 90.65 180 bottom
C5230  SCD1U10V2KX-5GP  [C402H22]  61.59 90.65 180 bottom
C5231  SCD1U10V2KX-5GP  [C402H22]  63.37 90.65 180 bottom
C5232  SCD1U10V2KX-5GP  [C402H22]  62.48 90.65 180 bottom
C5401  SCD1U16V2KX-3GP  [C402H22]  17.02 90.77 180 top
C5402  SCD1U16V2KX-3GP  [C402H22]  18.54 83.53 90 bottom
C5403  SCD1U16V2KX-3GP  [C402H22]  18.54 82.64 90 bottom
C5404  SCD1U16V2KX-3GP  [C402H22]  18.54 79.98 90 bottom
C5405  SCD1U16V2KX-3GP  [C402H22]  18.54 79.09 90 bottom
C5406  SCD1U16V2KX-3GP  [C402H22]  18.54 80.87 90 bottom
C5407  SCD1U16V2KX-3GP  [C402H22]  18.54 78.2 90 bottom
C5408  SCD1U16V2KX-3GP  [C402H22]  18.54 77.31 90 bottom
C5409  SCD1U16V2KX-3GP  [C402H22]  18.54 81.76 90 bottom
C5602  SCD01U50V2KX-1GP  [C402H22]  121.67 28.8 270 bottom
C5603  SCD01U50V2KX-1GP  [C402H22]  121.67 27.91 270 bottom
C5605  SC2D2U10V3KX-1GP  [C603H36]  135.76 31.08 270 bottom
C5606  SCD1U16V2KX-3GP  [C402H22]  135.64 29.69 270 bottom
C5615  SCD01U50V2KX-1GP  [C402H22]  119.89 26.13 270 bottom
C5616  SCD01U50V2KX-1GP  [C402H22]  119.89 27.02 270 bottom
C6201  SCD1U16V2KX-3GP  [C402H22]  118.62 25.37 90 top
C6202  SCD1U16V2KX-3GP  [C402H22]  26.67 14.06 90 bottom
C6204  SCD1U16V2KX-3GP  [C402H22]  101.98 25.24 180 bottom
C6401  SCD047U16V2KX-1-GP  [C402H22]  14.22 73.75 0 bottom
C6402  SCD1U16V2KX-3GP  [C402H22]  14.22 71.98 180 bottom
C6601  SC15P50V2JN-2-GP  [C402H22]  105.79 103.47 90 top
C6602  SCD1U10V2KX-5GP  [C402H22]  105.79 106.14 90 top
C6603  SCD1U10V2KX-5GP  [C402H22]  105.03 107.66 180 top
C6604  SCD1U10V2KX-5GP  [C402H22]  105.79 102.58 90 top
C6605  SCD01U50V2KX-1GP  [C402H22]  102.23 100.55 270 top
C6606  SCD01U50V2KX-1GP  [C402H22]  96.65 110.46 90 top
C6607  SCD01U50V2KX-1GP  [C402H22]  94.74 102.58 180 top
C6608  SC1U10V2KX-1GP  [C402H22]  103.12 99.66 270 top
C6609  SC15P50V2JN-2-GP  [C402H22]  105.79 105.12 90 top
C6610  SCD1U10V2KX-5GP  [C402H22]  165.35 16.99 0 top
C6611  SC10U6D3V3MX-L-GP  [C603H38]  162.81 17.37 270 top
C6701  SCD1U16V2KX-3GP  [C402H22]  156.97 21.68 90 top
C6702  SCD1U16V2KX-3GP  [C402H22]  158.62 16.48 90 top
C6703  SC10U6D3V3MX-GP  [C603H38]  159.26 21.68 90 top
CPU1  HASWELL-6-GP-U  [BGA1168M4024H64]  82.9 62.5 90 bottom
D2001  RB751V-40H-GP  [SOD323AKH38]  110.36 88.99 0 top
D2401  RB751V-40H-GP  [SOD323AKH38]  149.35 42.39 270 bottom
D2402  BAT54C-7-F-3-GP  [SOT23-2D4-312H48]  150.11 33.11 0 bottom
D2501  BAS40C-2-GP  [SOT-23-9H44]  143 64.86 270 bottom
D2601  RB551V30-1-GP  [SOD323AKH44]  139.95 69.06 90 top
D2701  BAT54C-7-F-3-GP  [SOT23-2D4-312H48]  31.11 33.37 0 bottom
D3602  BAS16-6-GP  [SOT23-2D4-312H44]  30.61 66.77 270 bottom
D4301  DA3X101F0L-1-GP  [SOT23-2D8-312H56]  90.93 26.26 0 bottom
D4302  DA3X101F0L-1-GP  [SOT23-2D8-312H56]  98.04 26.26 0 bottom
D4303  DA3X101F0L-1-GP  [SOT23-2D8-312H56]  94.49 26.26 0 bottom
D5201  BAT54C-7-F-3-GP  [SOT23-2D4-312H48]  75.56 97.38 90 top
D5202  BAT54C-7-F-3-GP  [SOT23-2D4-312H48]  70.48 97.38 270 top
D5401  BAW56-5-GP  [SOT-23-9H44]  19.94 74.9 90 bottom
D6701  BAT54A-7-F-2-GP  [SOT23-2D4-312H48]  150.11 37.18 180 bottom
DB1  ACES-CON10-14-GP  [87212-1002N]  125.35 106.65 180 bottom
DCIN1  ACES-CON8-13-GP-U1  [50224-0080N-W02]  19.6 91.5 0 bottom
DIMM1  DDR3-204P-215-GP-U  [DS2RK-20401-TP4B-U]  127.8 66 270 bottom
EC701  SCD1U10V2KX-5GP  [C402H22]  65.15 44.93 0 bottom
EC702  SCD1U10V2KX-5GP  [C402H22]  65.15 43.15 180 bottom
EC1701  SC4D7P50V2CN-1GP  [C402H22]  75.06 91.79 180 bottom
EC1702  SC1KP50V2KX-1GP  [C402H22]  85.85 96.11 90 top
EC1703  SC1KP50V2KX-1GP  [C402H22]  82.04 94.2 180 top
EC1704  SC1KP50V2KX-1GP  [C402H22]  97.79 90.14 90 top
EC1705  SC1KP50V2KX-1GP  [C402H22]  101.73 89.88 180 top
EC1706  SC1KP50V2KX-1GP  [C402H22]  76.33 90.77 180 top
EC1707  SCD1U10V2KX-5GP  [C402H22]  104.78 88.36 180 top
EC1801  SC10P50V2JN-4GP  [C402H22]  93.73 70.83 180 top
EC1802  SC10P50V2JN-4GP  [C402H22]  93.73 69.06 0 top
EC1901  SC10P50V2JN-4GP  [C402H22]  103.5 74.39 270 top
EC2501  SC4D7P50V2CN-1GP  [C402H22]  140.72 86.84 180 bottom
EC2502  SC4D7P50V2CN-1GP  [C402H22]  134.75 100.42 0 bottom
EC2503  SC10P50V2JN-4GP  [C402H22]  139.19 98.9 270 bottom
EC2701  SC10P50V2JN-4GP  [C402H22]  28.07 22.57 90 bottom
EC2703  SC1KP50V2KX-1GP  [C402H22]  24 36.29 270 bottom
EC2704  SC1KP50V2KX-1GP  [C402H22]  24 35.91 90 top
EC2705  SC1KP50V2KX-1GP  [C402H22]  22.1 37.18 0 bottom
EC2706  SC1KP50V2KX-1GP  [C402H22]  21.84 16.6 180 bottom
EC2707  SC1KP50V2KX-1GP  [C402H22]  22.48 22.83 0 bottom
EC2708  SC22P50V2JN-4GP  [C402H22]  31.88 23.97 90 top
EC2709  SC22P50V2JN-4GP  [C402H22]  31.88 24.86 90 top
EC2901  SC1KP50V2KX-1GP  [C402H22]  20.07 15.84 270 bottom
EC2902  SC1KP50V2KX-1GP  [C402H22]  18.67 13.05 180 bottom
EC2903  SC1KP50V2KX-1GP  [C402H22]  17.91 5.68 270 top
EC2904  SC1KP50V2KX-1GP  [C402H22]  19.18 9.24 90 top
EC2905  SC100P50V2JN-3GP  [C402H22]  16.64 23.59 90 bottom
EC2906  SC100P50V2JN-3GP  [C402H22]  18.29 33.62 270 top
EC2907  SC100P50V2JN-3GP  [C402H22]  22.35 19.65 0 bottom
EC2908  SC100P50V2JN-3GP  [C402H22]  18.29 32.23 180 bottom
EC4201  SC10U25V3MX-GP  [C603H40]  22.1 89.12 180 top
EC4202  SC1KP50V2KX-1GP  [C402H22]  20.95 88.99 180 top
EC4301  SC10P50V2JN-4GP  [C402H22]  91.31 28.67 270 bottom
EC4302  SC10P50V2JN-4GP  [C402H22]  93.98 28.67 90 bottom
EC4303  SCD1U25V2KX-GP  [C402H22]  88.39 27.27 0 bottom
EC4304  SCD1U50V3KX-GP  [C603H36]  90.3 23.21 270 bottom
EC4305  SC10P50V2JN-4GP  [C402H22]  96.77 28.67 270 bottom
EC4602  SC10P50V2JN-4GP  [C402H22]  47.75 50.01 90 top
EC4701  SCD1U50V3KX-GP  [C603H36]  50.04 78.07 0 bottom
EC4702  SCD1U10V2KX-5GP  [C402H22]  51.18 43.27 180 bottom
EC5205  SC22P50V2JN-4GP  [C402H22]  56.26 102.08 270 top
EC5206  SC22P50V2JN-4GP  [C402H22]  58.04 102.08 90 top
EC5207  SC6D8P50V2DN-GP  [C402H22]  52.58 96.61 270 top
EC5210  SCD1U25V2KX-GP  [C402H22]  44.32 91.66 180 bottom
EC5211  SC33P50V2JN-3GP  [C402H22]  30.73 92.93 90 bottom
EC6201  SC33P50V2JN-3GP  [C402H22]  113.92 23.46 90 top
EC6202  SC33P50V2JN-3GP  [C402H22]  111.89 23.46 270 top
EC6203  SC33P50V2JN-3GP  [C402H22]  124.71 24.48 90 top
EC6204  SC33P50V2JN-3GP  [C402H22]  124.71 26 90 top
EC8601  SC1KP50V2KX-1GP  [C402H22]  25.91 34.64 180 top
EC8602  SCD1U25V2KX-GP  [C402H22]  21.59 24.35 270 bottom
EC8603  SCD1U25V2KX-GP  [C402H22]  27.3 29.56 270 bottom
EC8604  SC1KP50V2KX-1GP  [C402H22]  27.3 33.37 90 top
EC8605  SC1U25V3KX-1-GP  [C603H36]  106.81 24.73 180 top
EC8606  SC2200P50V2KX-2GP  [C402H22]  70.23 30.57 90 top
EC8607  SCD1U25V2KX-GP  [C402H22]  20.32 72.1 180 bottom
EC8608  SCD1U25V2KX-GP  [C402H22]  18.85 85.39 90 top
EC8609  SCD1U25V2KX-GP  [C402H22]  76.96 102.46 0 top
EC8610  SCD1U25V2KX-GP  [C402H22]  33.78 59.78 180 top
EC8611  SCD1U25V2KX-GP  [C402H22]  35.56 29.81 0 top
EC8612  SCD1U25V2KX-GP  [C402H22]  148.34 69.31 270 top
EC8613  SCD1U25V2KX-GP  [C402H22]  155.07 64.99 90 top
EC8614  SCD1U25V2KX-GP  [C402H22]  145.03 35.02 270 top
EC8615  SCD1U25V2KX-GP  [C402H22]  25.78 37.05 90 bottom
EC8616  SCD1U25V2KX-GP  [C402H22]  29.84 91.66 0 top
EC8617  SC2200P50V2KX-2GP  [C402H22]  108.08 51.4 0 top
EC8618  SC2200P50V2KX-2GP  [C402H22]  106.68 51.4 0 top
EC8619  SC2200P50V2KX-2GP  [C402H22]  109.47 51.4 0 top
EC8620  SC2D2U10V3KX-1GP  [C603H36]  110.24 63.09 180 top
EC8621  SC2D2U10V3KX-1GP  [C603H36]  106.05 63.09 180 top
EC8622  SC2D2U10V3KX-1GP  [C603H36]  102.11 63.09 180 top
EC8623  SC1U25V3KX-1-GP  [C603H36]  54.61 90.52 270 top
EC8624  SC1U25V3KX-1-GP  [C603H36]  44.07 79.09 180 top
EC8625  SC1U25V3KX-1-GP  [C603H36]  27.56 71.72 270 top
EC8626  SC1U25V3KX-1-GP  [C603H36]  54.74 31.72 0 top
EC8627  SC1U25V3KX-1-GP  [C603H36]  86.87 34.26 90 top
EC8628  SC1U25V3KX-1-GP  [C603H36]  105.41 24.73 180 top
EC8629  SC1U25V3KX-1-GP  [C603H36]  43.18 31.97 0 top
EC8630  SC1KP50V2KX-1GP  [C402H22]  100.58 63.09 180 top
EC8631  SC1KP50V2KX-1GP  [C402H22]  99.82 51.4 0 top
EC8632  SCD1U25V2KX-GP  [C402H22]  57.15 36.29 0 bottom
EC8633  SC2200P50V2KX-2GP  [C402H22]  112.9 51.4 0 top
EC8634  SC2200P50V2KX-2GP  [C402H22]  111.38 51.4 0 top
EC8635  SC2200P50V2KX-2GP  [C402H22]  105.03 51.4 0 top
EC8636  SC2200P50V2KX-2GP  [C402H22]  103.5 51.4 0 top
EC8637  SC2200P50V2KX-2GP  [C402H22]  108.2 63.09 180 top
EC8638  SC2200P50V2KX-2GP  [C402H22]  104.39 63.09 180 top
ED1217  AZ5725-01FDR7G-GP  [SOD882-10D6-1H20]  129.92 42 270 top
ED2901  AZ2025-01H-R7G-GP  [SOD-523-4H28]  18.8 37.05 180 bottom
ED2902  AZ2025-01H-R7G-GP  [SOD-523-4H28]  19.51 18.51 0 bottom
ED2903  AZ2025-01H-R7G-GP  [SOD-523-4H28]  17.7 18.51 0 bottom
ED2904  AZ2025-01H-R7G-GP  [SOD-523-4H28]  20.7 37.05 180 bottom
ED2905  AZ2025-01H-R7G-GP  [SOD-523-4H28]  20.19 37.05 0 top
ED2906  AZ2025-01H-R7G-GP  [SOD-523-4H28]  22.1 37.05 0 top
EL4201  0R0805-PAD-2-GP-U  [0R0805-PAD-1-U]  22.61 81.25 180 bottom
EL4203  0R0805-PAD-2-GP-U  [0R0805-PAD-1-U]  22.1 81.25 0 top
EL4204  0R0805-PAD-2-GP-U  [0R0805-PAD-1-U]  23.9 81.25 0 top
EU3401  ESD3V3U4ULC-GP  [LGA9G2310H13]  17.91 62.96 270 bottom
EU3402  AZC099-04S-1-GP  [SOT-6H58]  19.18 58.77 270 bottom
EU3403  ESD3V3U4ULC-GP  [LGA9G2310H13]  18.8 44.93 270 bottom
EU3404  AZC099-04S-1-GP  [SOT-6H58]  20.19 40.61 270 bottom
F5201  POLYSW-1D1A24V-GP-U  [POLYSW-4633-UH43]  65.41 97.76 270 top
F5202  POLYSW-D5A6V-1-GP  [POLYSW-2114H50]  40.77 92.17 270 bottom
F5203  POLYSW-1D1A24V-GP-U  [POLYSW-4633-UH43]  31.37 98.27 90 top
F5204  POLYSW-1D1A6V-9-GP-U  [POLYSW-2114H30]  33.66 92.17 90 bottom
F5401  POLYSW-1D1A6V-9-GP-U  [POLYSW-2114H30]  19.43 91.41 0 top
F6201  POLYSW-D5A6V-1-GP  [POLYSW-2114H50]  29.97 14.83 180 bottom
FAN1  ACES-CON4-29-GP  [50224-0040N-001]  142.8 77 0 bottom
G1901  GAP-OPEN  [CON2O-U]  96.52 104.87 90 bottom
H1  HOLE335R178-GP  [HOLE335R178]  23.8 101.5 180 bottom
H2  HOLE335R229-GP  [HOLE335R229]  11.6 17.5 180 bottom
H3  HOLE335R229-GP  [HOLE335R229]  76.8 18 180 bottom
H4  HOLE335R229-GP  [HOLE335R229]  147.8 20.5 180 bottom
H5  HOLE335R178-GP  [HOLE335R178]  140.8 106 180 bottom
H6  HOLE335R178-GP  [HOLE335R178]  70.3 104.5 180 bottom
HDA27  ALC3234-CG-GP  [QFN48J6-G465H40]  23.88 25.11 270 top
HDD1  FOX-CON20-1-GP-U1  [GS12201-1011-9H]  133.8 25 0 bottom
HDMI1  SKT-HDMI23-15-GP-U  [SKT-HDMI23-178128-2]  4.3 83.1 90 bottom
HOMBD1  PSC-CON16-GP  [AYF531635]  33.8 99 270 bottom
HPMIC1  AUDIO-JK443-GP  [2SJ3095-013111F]  4.55 28.9 90 bottom
HS1  STF237R125H42-1-GP  [STF237R125H42]  59.9 60 180 bottom
HS2  STF237R125H42-1-GP  [STF237R125H42]  91.85 87.15 180 bottom
HS3  STF237R125H42-1-GP  [STF237R125H42]  91.85 32.8 180 bottom
IOBD1  STAR-CON40-GP  [LVD-A40SFYG]  149.8 58.5 90 bottom
KB1  ACES-CON26-13-GP-U  [50588-02601-001-U]  158.8 30.5 270 bottom
KBC24  NPCE285PA0DX-GP  [LQFP128H63]  154.94 46.96 90 top
KBLIT1  ACES-CON4-39-GP  [50503-0040N-W01]  24.8 8 180 bottom
L1101  0R0603-PAD-2-GP-U  [0R0603-PAD-1-U]  63.37 70.33 270 bottom
L1102  0R0603-PAD-2-GP-U  [0R0603-PAD-1-U]  62.48 72.99 0 bottom
L1103  IND-2D2UH-196-GP  [L603H40]  64.64 68.55 180 top
L1104  IND-2D2UH-196-GP  [L603H40]  63.5 68.8 270 bottom
LCD1  ACES-CON40-11-GP  [LVD-A40SFYG]  55.8 96 180 bottom
LIDSW1  S-5712ACDL1-M3T1U-GP  [SOT23-2D8-123H52]  7.85 73.2 0 bottom
NOREF  *  [unnamed]  -0.7 152.55 0 top
NOREF#2  -  [#2]  162.31 12.03 0 top
NOREF#3  -  [unnamed]  -2.55 14.32 0 top
NOREF#4  -  [#2]  65.28 3.52 0 top
NOREF#5  -  [#2]  56.52 61.18 0 top
NOREF#6  *  [unnamed]  164.21 28.8 0 top
NOREF#7  -  [unnamed]  -1.57 147.49 0 top
NOREF#8  -  [#2]  0 2 0 top
NOREF#9  -  [#2]  0 2 0 top
NOREF#10  *  [unnamed]  165.86 12.03 0 top
NOREF#11  *  [unnamed]  18.29 16.1 0 top
NOREF#12  *  [unnamed]  135 105.38 0 top
NOREF#13  -  [#2]  -5.7 137.55 0 top
NOREF#14  -  [unnamed]  165.1 76.93 0 top
NOREF#15  -  [unnamed]  163.89 153.93 0 top
NOREF#16  -  [#2]  0 2 0 top
NOREF#17  -  [#2]  152.15 161.77 180 top
NOREF#18  *  [unnamed]  169 153.67 0 top
NOREF#19  *  [unnamed]  144.15 60.29 0 top
NOREF#20  *  [unnamed]  3.3 5.17 0 top
NOREF#21  *  [unnamed]  -0.7 18.45 0 top
NOREF#22  -  [unnamed]  134 108.4 90 top
NOREF#23  -  [unnamed]  112.9 8.73 0 top
NOREF#24  *  [unnamed]  32.51 28.92 0 top
NOREF#25  -  [#2]  172.21 83.03 270 top
NOREF#26  -  [unnamed]  37.34 137.64 0 top
NOREF#27  -  [unnamed]  172 15.11 0 top
NOREF#28  -  [unnamed]  6 16.9 0 top
NOREF#29  -  [#2]  -1.65 103.6 180 bottom
NOREF#30  -  [#2]  135.51 19.02 180 bottom
NOREF#31  *  [unnamed]  -0.7 152.55 180 bottom
NOREF#32  *  [unnamed]  3.3 5.17 180 bottom
NOREF#33  -  [#2]  161.16 57.88 180 bottom
NOREF#34  -  [#2]  101.35 55.59 180 bottom
NOREF#35  -  [#2]  166.75 70.58 180 bottom
NOREF#36  *  [unnamed]  69.19 90.37 180 bottom
NOREF#37  *  [unnamed]  169 153.67 180 bottom
NOREF#38  -  [#2]  86.87 108.81 180 bottom
NOREF#39  -  [#2]  79.76 91.03 180 bottom
NOREF#40  *  [unnamed]  -0.7 18.45 180 bottom
NOREF#41  -  [#2]  162.31 12.03 180 bottom
NOREF#42  -  [#2]  40.13 132.05 180 bottom
NOREF#43  -  [#2]  7.24 8.73 180 bottom
NOREF#44  -  [#2]  157.61 80.36 180 bottom
NOREF#45  *  [unnamed]  92.71 38.07 180 bottom
NOREF#46  *  [unnamed]  135 105.38 180 bottom
NOREF#47  *  [unnamed]  165.86 12.03 180 bottom
NOREF#48  -  [#2]  31.37 42.89 90 bottom
NOREF#49  -  [#2]  172.97 80.74 90 bottom
PC4201  SC1U25V3KX-1-GP  [C603H36]  42.67 29.69 180 bottom
PC4202  SCD1U25V3KX-GP  [C603H36]  36.58 29.3 180 bottom
PC4203  SCD01U50V2KX-1GP  [C402H22]  36.07 23.21 90 bottom
PC4204  SCD01U50V2KX-1GP  [C402H22]  36.07 22.32 90 bottom
PC4205  SCD01U50V2KX-1GP  [C402H22]  36.07 24.1 90 bottom
PC4206  SC10U25V5KX-GP  [C805H56]  36.32 26 0 bottom
PC4401  SCD1U25V2KX-GP  [C402H22]  49.02 16.48 180 top
PC4402  SCD01U50V2KX-1GP  [C402H22]  37.85 11.52 0 top
PC4403  SC10U25V5KX-GP  [C805H56]  73.53 29.18 270 bottom
PC4404  SC1U25V3KX-1-GP  [C603H36]  35.94 4.16 0 top
PC4405  SCD01U50V2KX-1GP  [C402H22]  35.94 4.03 180 bottom
PC4406  SC330P50V3KX-GP  [C603]  51.94 29.81 180 top
PC4407  SC10U25V5KX-GP  [C805H56]  48.13 26.13 0 bottom
PC4408  SC10U25V5KX-GP  [C805H56]  73.53 32.99 270 bottom
PC4409  SC10U25V5KX-GP  [C805H56]  73.53 31.08 270 bottom
PC4410  SC1U25V3KX-1-GP  [C603H36]  38.23 18.51 270 top
PC4411  SC10U25V5KX-GP  [C805H56]  48.13 21.18 180 bottom
PC4412  SCD1U25V2KX-GP  [C402H22]  49.02 14.7 0 top
PC4413  SCD1U25V2KX-GP  [C402H22]  49.53 26.13 0 bottom
PC4414  SCD47U6D3V2KX-1-GP  [C402H22]  42.93 10.13 180 bottom
PC4415  SC10U25V5KX-GP  [C805H56]  79.78 27.96 0 bottom
PC4416  SCD1U25V2KX-GP  [C402H22]  37.34 16.35 270 top
PC4417  SC1U25V3KX-1-GP  [C603H36]  78.87 30.96 180 top
PC4418  SCD1U25V2KX-GP  [C402H22]  35.53 14.78 90 top
PC4419  SCD01U50V2KX-1GP  [C402H22]  33.53 3.14 0 top
PC4420  SC1U25V3KX-1-GP  [C603H36]  76.96 23.46 90 top
PC4421  SCD047U25V3KX-3-GP  [C603H36]  40.77 18.64 0 top
PC4422  SC2D2U25V3KX-GP  [C603H38]  43.56 18.64 180 top
PC4423  SCD1U25V2KX-GP  [C402H22]  75.06 28.42 90 top
PC4424  SCD01U25V2KX-3GP  [C402H22]  84.2 27.4 90 bottom
PC4425  SC10U25V5KX-GP  [C805H56]  51.94 21.18 180 bottom
PC4426  SC100P50V2JN-3GP  [C402H22]  32.64 3.14 0 top
PC4427  SC10U25V5KX-GP  [C805H56]  53.85 21.18 180 bottom
PC4428  SCD1U25V2KX-GP  [C402H22]  37.85 15.08 0 top
PC4429  SCD1U25V2KX-GP  [C402H22]  49.91 15.59 0 top
PC4430  SC10U25V5KX-GP  [C805H56]  71.25 22.7 180 bottom
PC4431  SC1U25V3KX-1-GP  [C603H36]  71.75 30.19 180 top
PC4432  SC1U25V3KX-1-GP  [C603H36]  35.31 15.84 270 top
PC4433  SCD1U25V2KX-GP  [C402H22]  38.23 17.37 270 top
PC4434  SC10U25V5KX-GP  [C805H56]  50.04 21.18 180 bottom
PC4435  SC100P50V2JN-3GP  [C402H22]  29.46 3.65 270 top
PC4436  SC100P50V2JN-3GP  [C402H22]  38.48 7.59 0 top
PC4437  SC100P50V2JN-3GP  [C402H22]  39.37 7.59 0 top
PC4438  SC1U25V3KX-1-GP  [C603H36]  48.03 10.71 270 top
PC4439  SC10U25V5KX-GP  [C805H56]  76.96 23.46 90 bottom
PC4440  SC10U25V5KX-GP  [C805H56]  81.58 27.96 0 bottom
PC4441  SC10U25V5KX-GP  [C805H56]  58.55 36.29 0 bottom
PC4442  SC10U25V5KX-GP  [C805H56]  60.38 36.29 0 bottom
PC4509  SC10U25V5KX-GP  [C805H56]  31.75 73.12 0 bottom
PC4516  SCD1U25V3KX-GP  [C603H36]  31.37 65.5 90 top
PC4517  SCD1U10V2KX-4GP  [C402H20]  40.13 86.33 270 bottom
PC4518  SCD1U10V2KX-4GP  [C402H20]  29.46 89.88 270 bottom
PC4519  SC10U25V5KX-GP  [C805H56]  38.99 73.12 0 bottom
PC4520  SC330P50V3KX-GP  [C603]  38.48 74.01 90 top
PC4522  SC18P50V2JN-1-GP  [C402H22]  33.15 62.07 180 top
PC4523  SC18P50V2JN-1-GP  [C402H22]  37.85 62.07 180 top
PC4524  SC4D7U6D3V3KX-GP  [C603H36]  35.81 69.82 180 top
PC4525  SCD1U50V3KX-GP  [C603H36]  31.62 73.12 180 top
PC4526  SC4D7U6D3V3KX-GP  [C603H36]  35.81 61.69 0 top
PC4527  SC10U25V5KX-GP  [C805H56]  41.78 69.69 180 bottom
PC4528  SC10U25V5KX-GP  [C805H56]  33.66 73.12 0 bottom
PC4529  SC10U25V5KX-GP  [C805H56]  40.79 73.12 0 bottom
PC4530  SCD1U50V3KX-GP  [C603H36]  40.77 73.12 180 top
PC4531  SCD01U50V2KX-1GP  [C402H22]  36.96 69.56 180 top
PC4535  SCD1U25V3KX-GP  [C603H36]  40.26 65.5 270 top
PC4536  SC560P50V-GP  [C603]  29.72 73.63 90 top
PC4601  SC1U6D3V2KX-GP  [C402H22]  45.59 48.74 180 top
PC4602  SC4700P50V2KX-1GP  [C402H22]  40.46 55.59 180 top
PC4603  SC1KP50V2KX-1GP  [C402H22]  39.62 54.7 0 top
PC4604  SC470P50V2JN-GP  [C402H22]  37.72 47.21 180 top
PC4605  SCD1U10V2KX-5GP  [C402H22]  42.16 44.93 90 bottom
PC4606  SCD33U6D3V2KX-1-GP  [C402H22]  38.86 45.43 180 top
PC4607  SC10U6D3V3MX-GP  [C603H38]  40.51 45.31 270 top
PC4608  SC1500P50V2KX-2GP  [C402H22]  35.94 46.32 0 top
PC4701  SC820P50V2KX-1GP  [C402H22]  46.61 68.42 0 bottom
PC4702  SC10U25V5KX-GP  [C805H56]  48.39 78.07 0 bottom
PC4703  SC10U25V5KX-GP  [C805H56]  46.48 78.07 0 bottom
PC4704  SC10U25V5KX-GP  [C805H56]  46.61 74.01 180 bottom
PC4705  SC2D2U10V3KX-1GP  [C603H36]  54.36 69.18 270 bottom
PC4706  SCD22U25V3KX-GP  [C603H40]  53.98 77.56 180 bottom
PC4707  SCD15U25V3KX-2-GP  [C603H38]  38.48 52.42 270 bottom
PC4708  SC1000P100V3KX-GP  [C603H36]  48.26 74.01 180 bottom
PC4709  SC22U6D3V3MX-1-GP  [C603H40]  77.34 58.64 90 top
PC4710  SC22U6D3V3MX-1-GP  [C603H40]  77.34 56.99 90 top
PC4711  SC22U6D3V3MX-1-GP  [C603H40]  77.34 60.55 90 top
PC4714  SC22U6D3V3MX-1-GP  [C603H40]  52.83 42.97 0 top
PC4715  SC22U6D3V5MX-2GP  [C805H58]  52.83 47.92 0 bottom
PC4716  SC22U6D3V5MX-2GP  [C805H58]  61.09 54.07 0 bottom
PC4719  SC22U6D3V3MX-1-GP  [C603H40]  77.34 62.58 90 top
PC4720  SC22U6D3V3MX-1-GP  [C603H40]  82.3 48.86 180 top
PC4721  SC22U6D3V3MX-1-GP  [C603H40]  77.34 64.48 90 top
PC4722  SC22U6D3V3MX-1-GP  [C603H40]  77.34 66.26 90 top
PC4724  SC22U6D3V5MX-2GP  [C805H58]  59.18 54.07 0 bottom
PC4725  SC22U6D3V5MX-2GP  [C805H58]  56.64 47.92 0 bottom
PC4726  SC22U6D3V5MX-2GP  [C805H58]  52.58 43.27 180 bottom
PC4727  SC22U6D3V5MX-2GP  [C805H58]  54.74 47.92 0 bottom
PC4728  SC22U6D3V5MX-2GP  [C805H58]  62.99 54.07 0 bottom
PC4729  SC22U6D3V3MX-1-GP  [C603H40]  77.34 51.02 90 top
PC4730  SC22U6D3V3MX-1-GP  [C603H40]  78.23 48.86 180 top
PC4731  SC22U6D3V3MX-1-GP  [C603H40]  84.96 48.86 180 top
PC4732  SC22U6D3V3MX-1-GP  [C603H40]  77.34 53.05 90 top
PC4733  SC22U6D3V3MX-1-GP  [C603H40]  77.34 55.09 90 top
PC4734  SC22U6D3V5MX-2GP  [C805H58]  56.39 43.27 180 bottom
PC4735  SC22U6D3V3MX-1-GP  [C603H40]  52.58 58.39 180 top
PC4736  SC22U6D3V5MX-2GP  [C805H58]  54.48 43.27 180 bottom
PC4737  SC22U6D3V5MX-2GP  [C805H58]  58.29 43.27 180 bottom
PC4738  SC22U6D3V3MX-1-GP  [C603H40]  54.74 42.97 0 top
PC4739  SC22U6D3V3MX-1-GP  [C603H40]  56.64 42.97 0 top
PC4740  SC22U6D3V3MX-1-GP  [C603H40]  53.98 58.39 180 top
PC4741  SC22U6D3V3MX-1-GP  [C603H40]  55.37 58.39 180 top
PC4742  SC22U6D3V3MX-1-GP  [C603H40]  58.93 42.97 0 top
PC4743  SC22U6D3V5MX-2GP  [C805H58]  57.28 54.07 0 bottom
PC4801  SCD1U10V2KX-5GP  [C402H22]  47.37 88.61 0 bottom
PC4802  SC220P50V2KX-3GP  [C402H22]  45.59 87.98 180 bottom
PC4803  SCD1U50V3KX-L-GP  [C603H36]  56.9 86.2 0 bottom
PC4804  SC4D7U25V5KX-L2-GP  [C805H58]  44.07 80.99 270 bottom
PC4805  SC22U6D3V5MX-L3-GP  [C805H58]  60.07 83.79 270 bottom
PC4806  SCD1U25V3KX-L-GP  [C603H36]  43.56 83.91 90 top
PC4807  SC1U6D3V2KX-GP  [C402H22]  42.04 87.98 0 bottom
PC4808  SC4D7U25V5KX-L2-GP  [C805H58]  44.07 79.09 270 bottom
PC4809  SC2D2U6D3V2MX-GP  [C402H22]  42.93 87.98 0 bottom
PC4810  SC22U6D3V5MX-L3-GP  [C805H58]  60.07 79.98 270 bottom
PC4811  SC22U6D3V5MX-L3-GP  [C805H58]  58.55 86.2 0 bottom
PC4812  SC22U6D3V5MX-L3-GP  [C805H58]  60.07 81.88 270 bottom
PC4813  SC22U6D3V5MX-L3-GP  [C805H58]  57.28 80.49 180 bottom
PC4901  SC22U6D3V5MX-L3-GP  [C805H58]  142.75 54.2 270 bottom
PC4902  SCD1U16V2KX-3GP  [C402H22]  135.64 52.8 90 bottom
PC4903  SC22U6D3V5MX-L3-GP  [C805H58]  135.64 54.2 90 bottom
PC4904  SC22U6D3V5MX-L3-GP  [C805H58]  135.64 56.1 90 bottom
PC4905  SC22U6D3V5MX-L3-GP  [C805H58]  142.75 56.1 270 bottom
PC4906  SC10U25V5KX-GP  [C805H56]  143.64 42.64 0 bottom
PC4907  SCD01U50V2KX-L-GP  [C402H22]  142.11 43.02 0 bottom
PC4908  SC10U25V5KX-GP  [C805H56]  139.06 41.12 90 bottom
PC4909  SCD1U10V2KX-5GP  [C402H22]  135.76 46.45 90 bottom
PC4910  SC1U6D3V2KX-L-1-GP  [C402H22]  138.3 41.12 0 top
PC4911  SC1U10V2KX-1GP  [C402H22]  138.05 80.99 270 bottom
PC4912  SC220P50V2KX-3GP  [C402H22]  135.76 41.88 270 bottom
PC4913  SC1U6D3V2KX-L-1-GP  [C402H22]  135.76 40.99 90 bottom
PC4914  SC22U6D3V3MX-1-GP  [C603H40]  136.02 74.9 90 top
PC4915  SC10U6D3V3MX-GP  [C603H38]  138.05 72.23 270 bottom
PC4916  SCD1U10V2KX-5GP  [C402H22]  135.25 80.99 90 bottom
PC4917  SCD1U25V3KX-GP  [C603H36]  139.7 44.67 180 top
PC4918  SCD1U10V2KX-5GP  [C402H22]  138.05 73.37 270 bottom
PC5101  SCD1U10V2KX-5GP  [C402H22]  50.04 91.03 0 bottom
PC5108  SC1U6D3V2KX-GP  [C402H22]  50.04 89.12 0 bottom
PC5109  SC1U6D3V2KX-GP  [C402H22]  55.63 89.12 0 bottom
PD4201  1SMB22AT3G-GP-U1  [D5436AKH98]  42.16 33.5 90 bottom
PD4203  DA3X101F0L-1-GP  [SOT23-2D8-312H56]  41.53 100.93 180 top
PD4204  PESD24VS2UT-GP  [SOT-23-10H44]  24.13 95.09 270 top
PD4302  SMF18AT1G-GP  [SOD123FLAKH40]  90.81 23.84 0 top
PD4401  CH035H-40PT0-GP  [SOD323AKH40]  45.34 18.51 180 top
PD4402  V8P10-5300M3-86A-GP  [SMPC4665-3P-UH48]  87.12 26 90 top
PD4403  1N4148WS-7-F-GP  [SOD323AKH42]  33.15 10.25 270 bottom
PD4405  CH035H-40PT0-GP  [SOD323AKH40]  33.02 16.6 180 top
PD4406  CH035H-40PT0-GP  [SOD323AKH40]  34.67 12.03 180 top
PG4401  GAP-CLOSE-PWR-3-GP  [GAP-CLOSE-PWR-3]  43.18 7.71 270 top
PG4402  GAP-CLOSE-PWR-3-GP  [GAP-CLOSE-PWR-3]  45.72 26.76 90 bottom
PG4403  GAP-CLOSE-PWR-3-GP  [GAP-CLOSE-PWR-3]  76.71 25.62 0 bottom
